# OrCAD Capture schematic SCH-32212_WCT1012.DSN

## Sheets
1 PAGE01- Revision History: title: WCT-15W1CFFPDSCT; rev: B; company: Freescale Semiconductor; note: SCH-29323 PDF: SPF-29323; note: 6501 William Cannon Drive West; note: Austin, TX 78735-8598
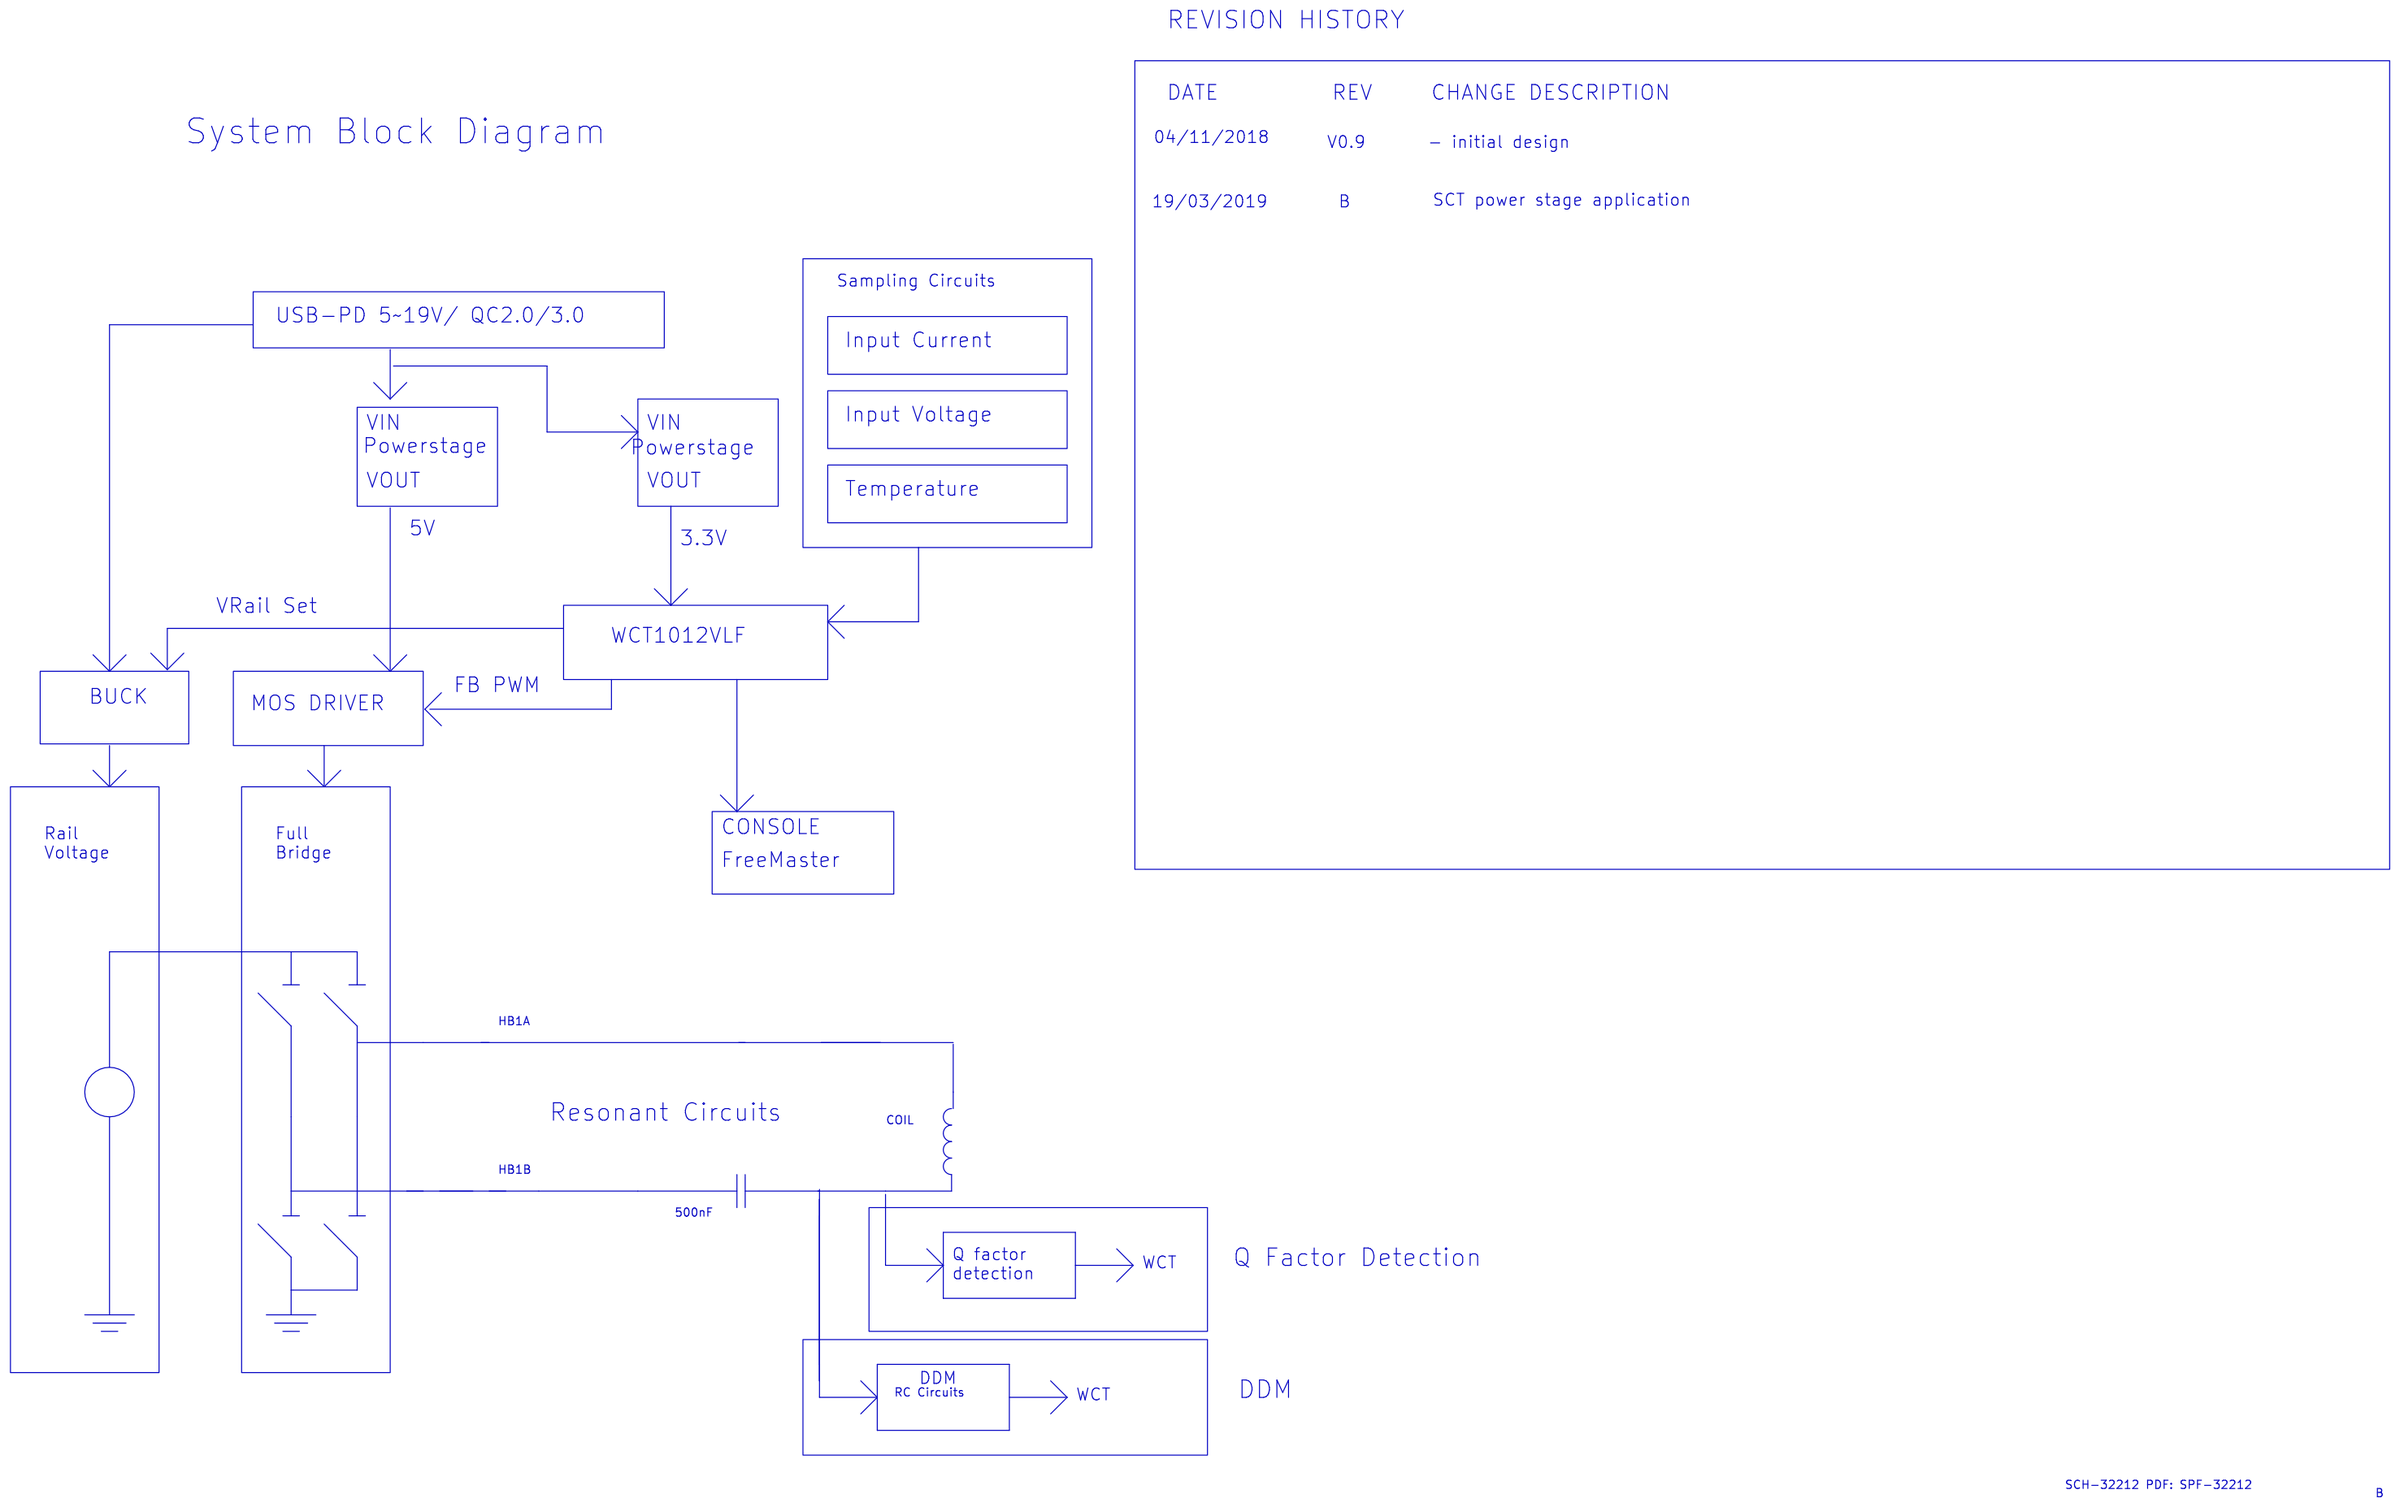
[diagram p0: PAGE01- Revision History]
2 PAGE02- Input Circuits: size B
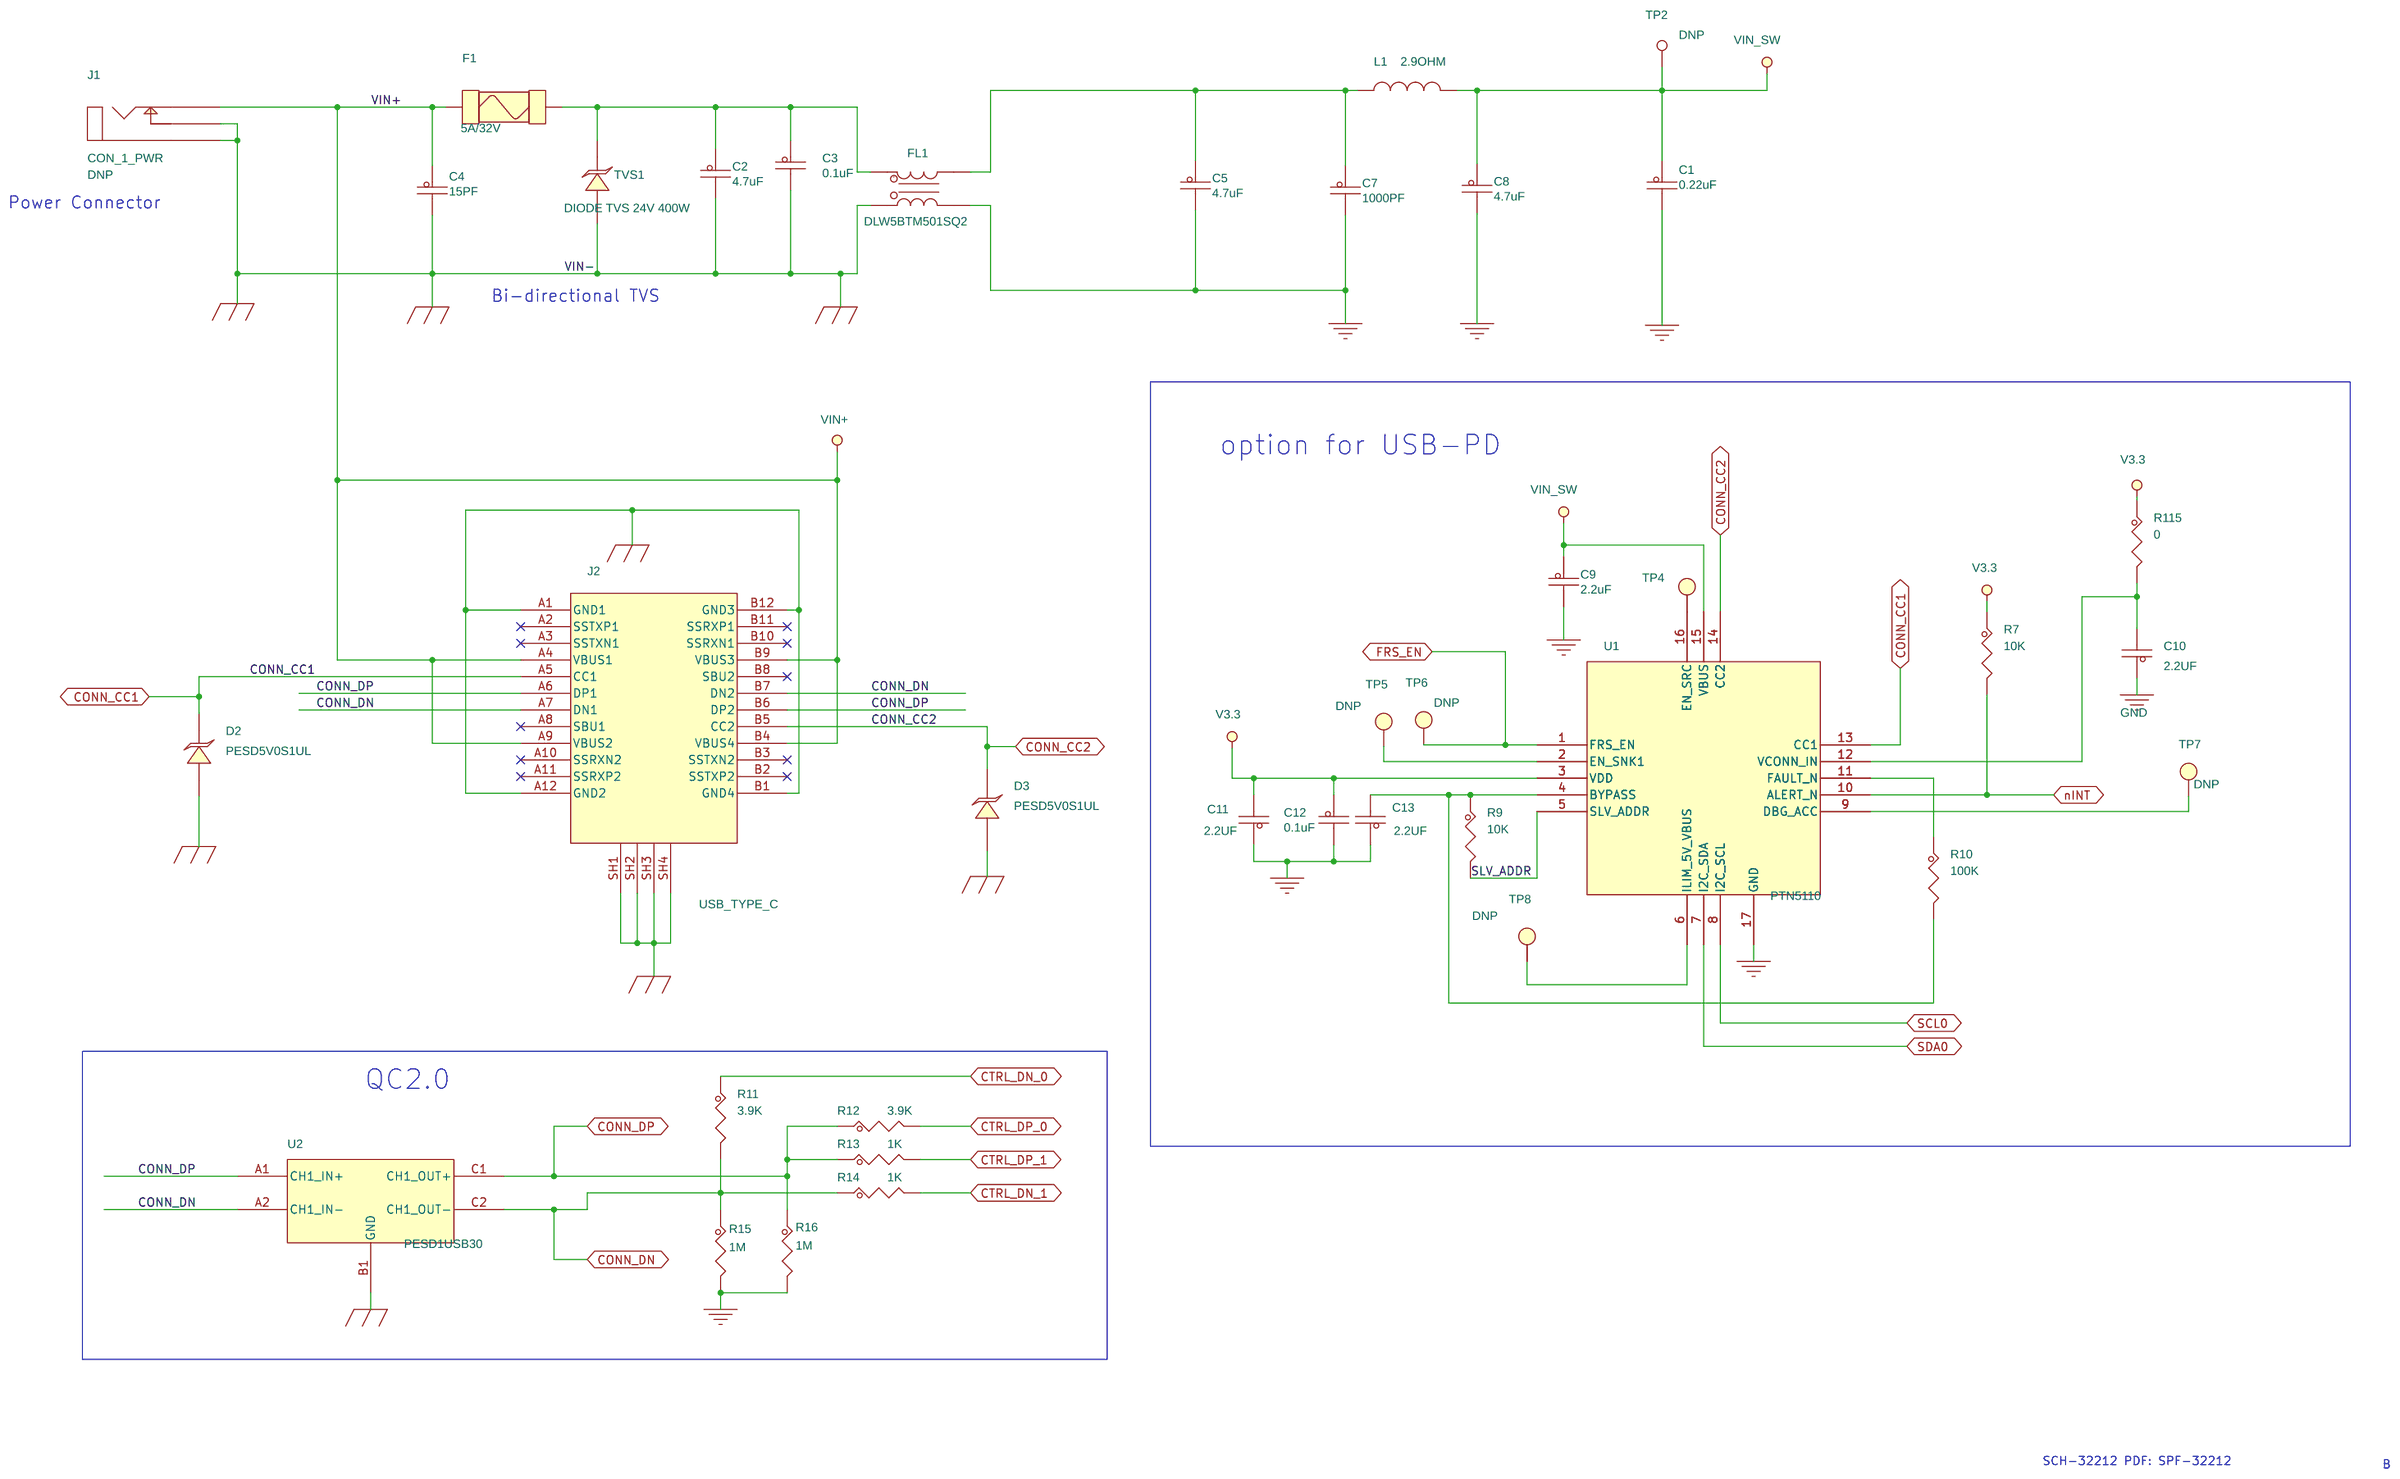
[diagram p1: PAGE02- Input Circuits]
3 PAGE03- Microprocessor: size B
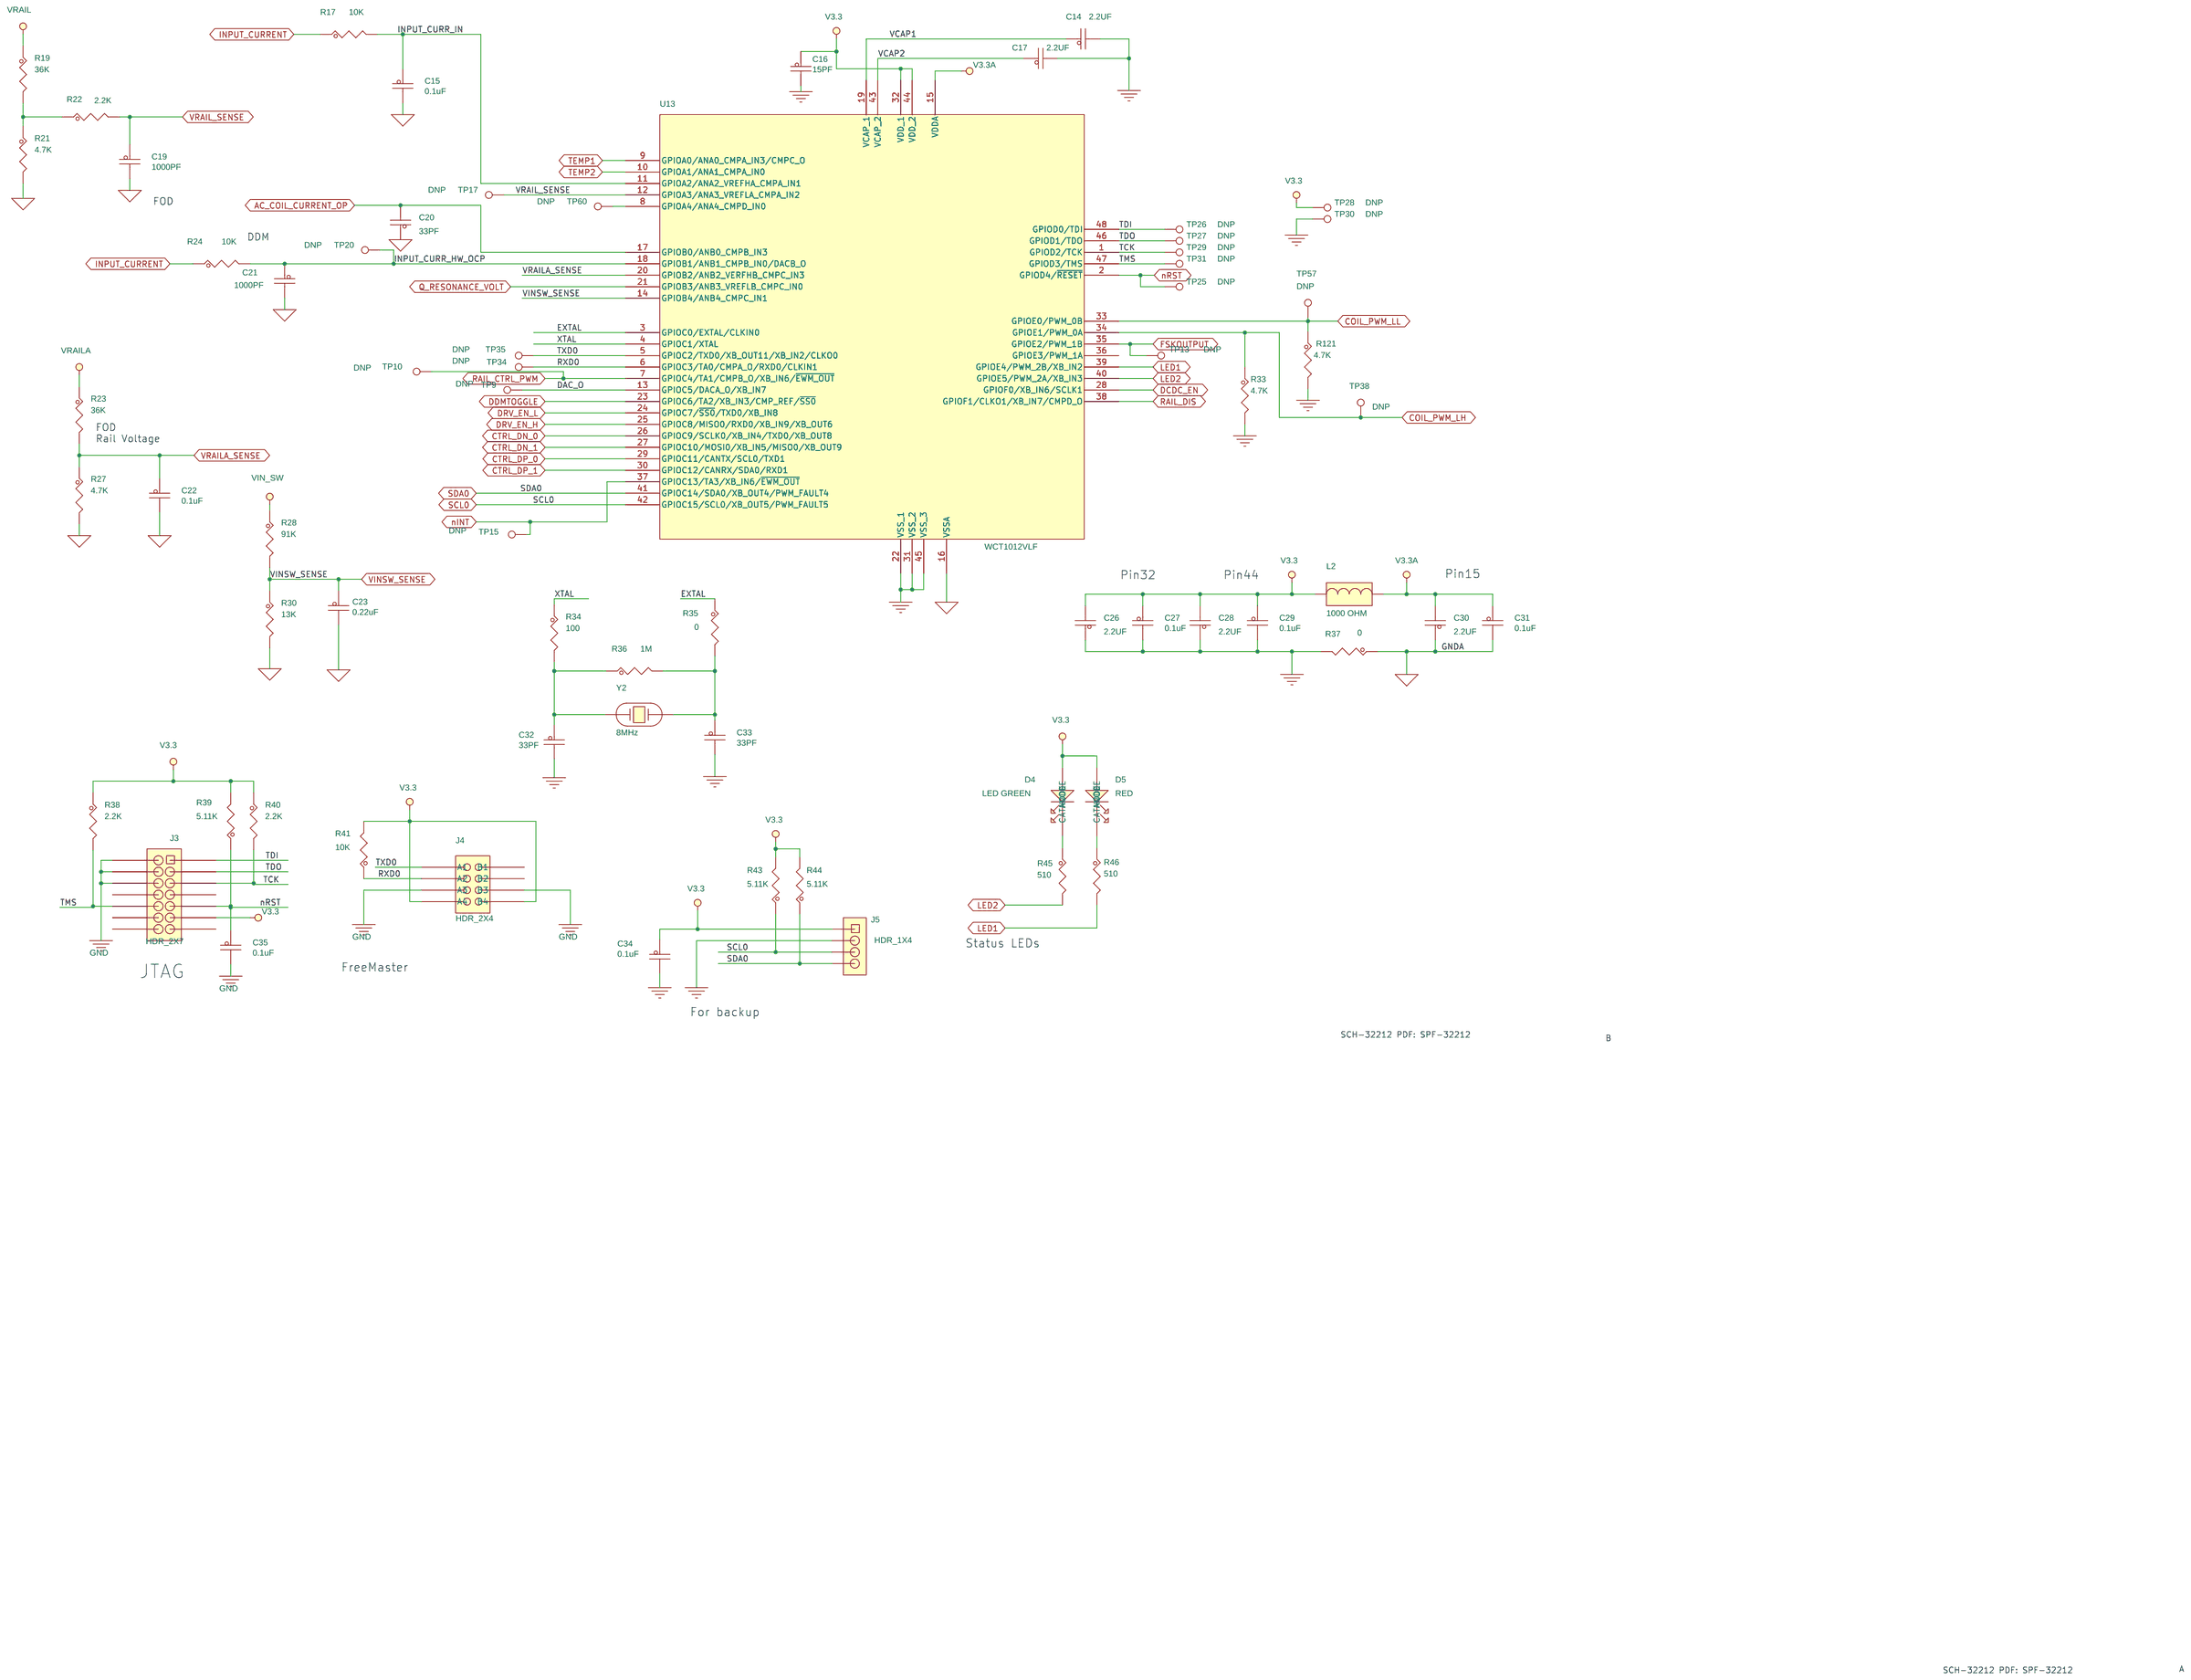
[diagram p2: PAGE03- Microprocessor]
4 PAGE04- VRail Circuits: size B
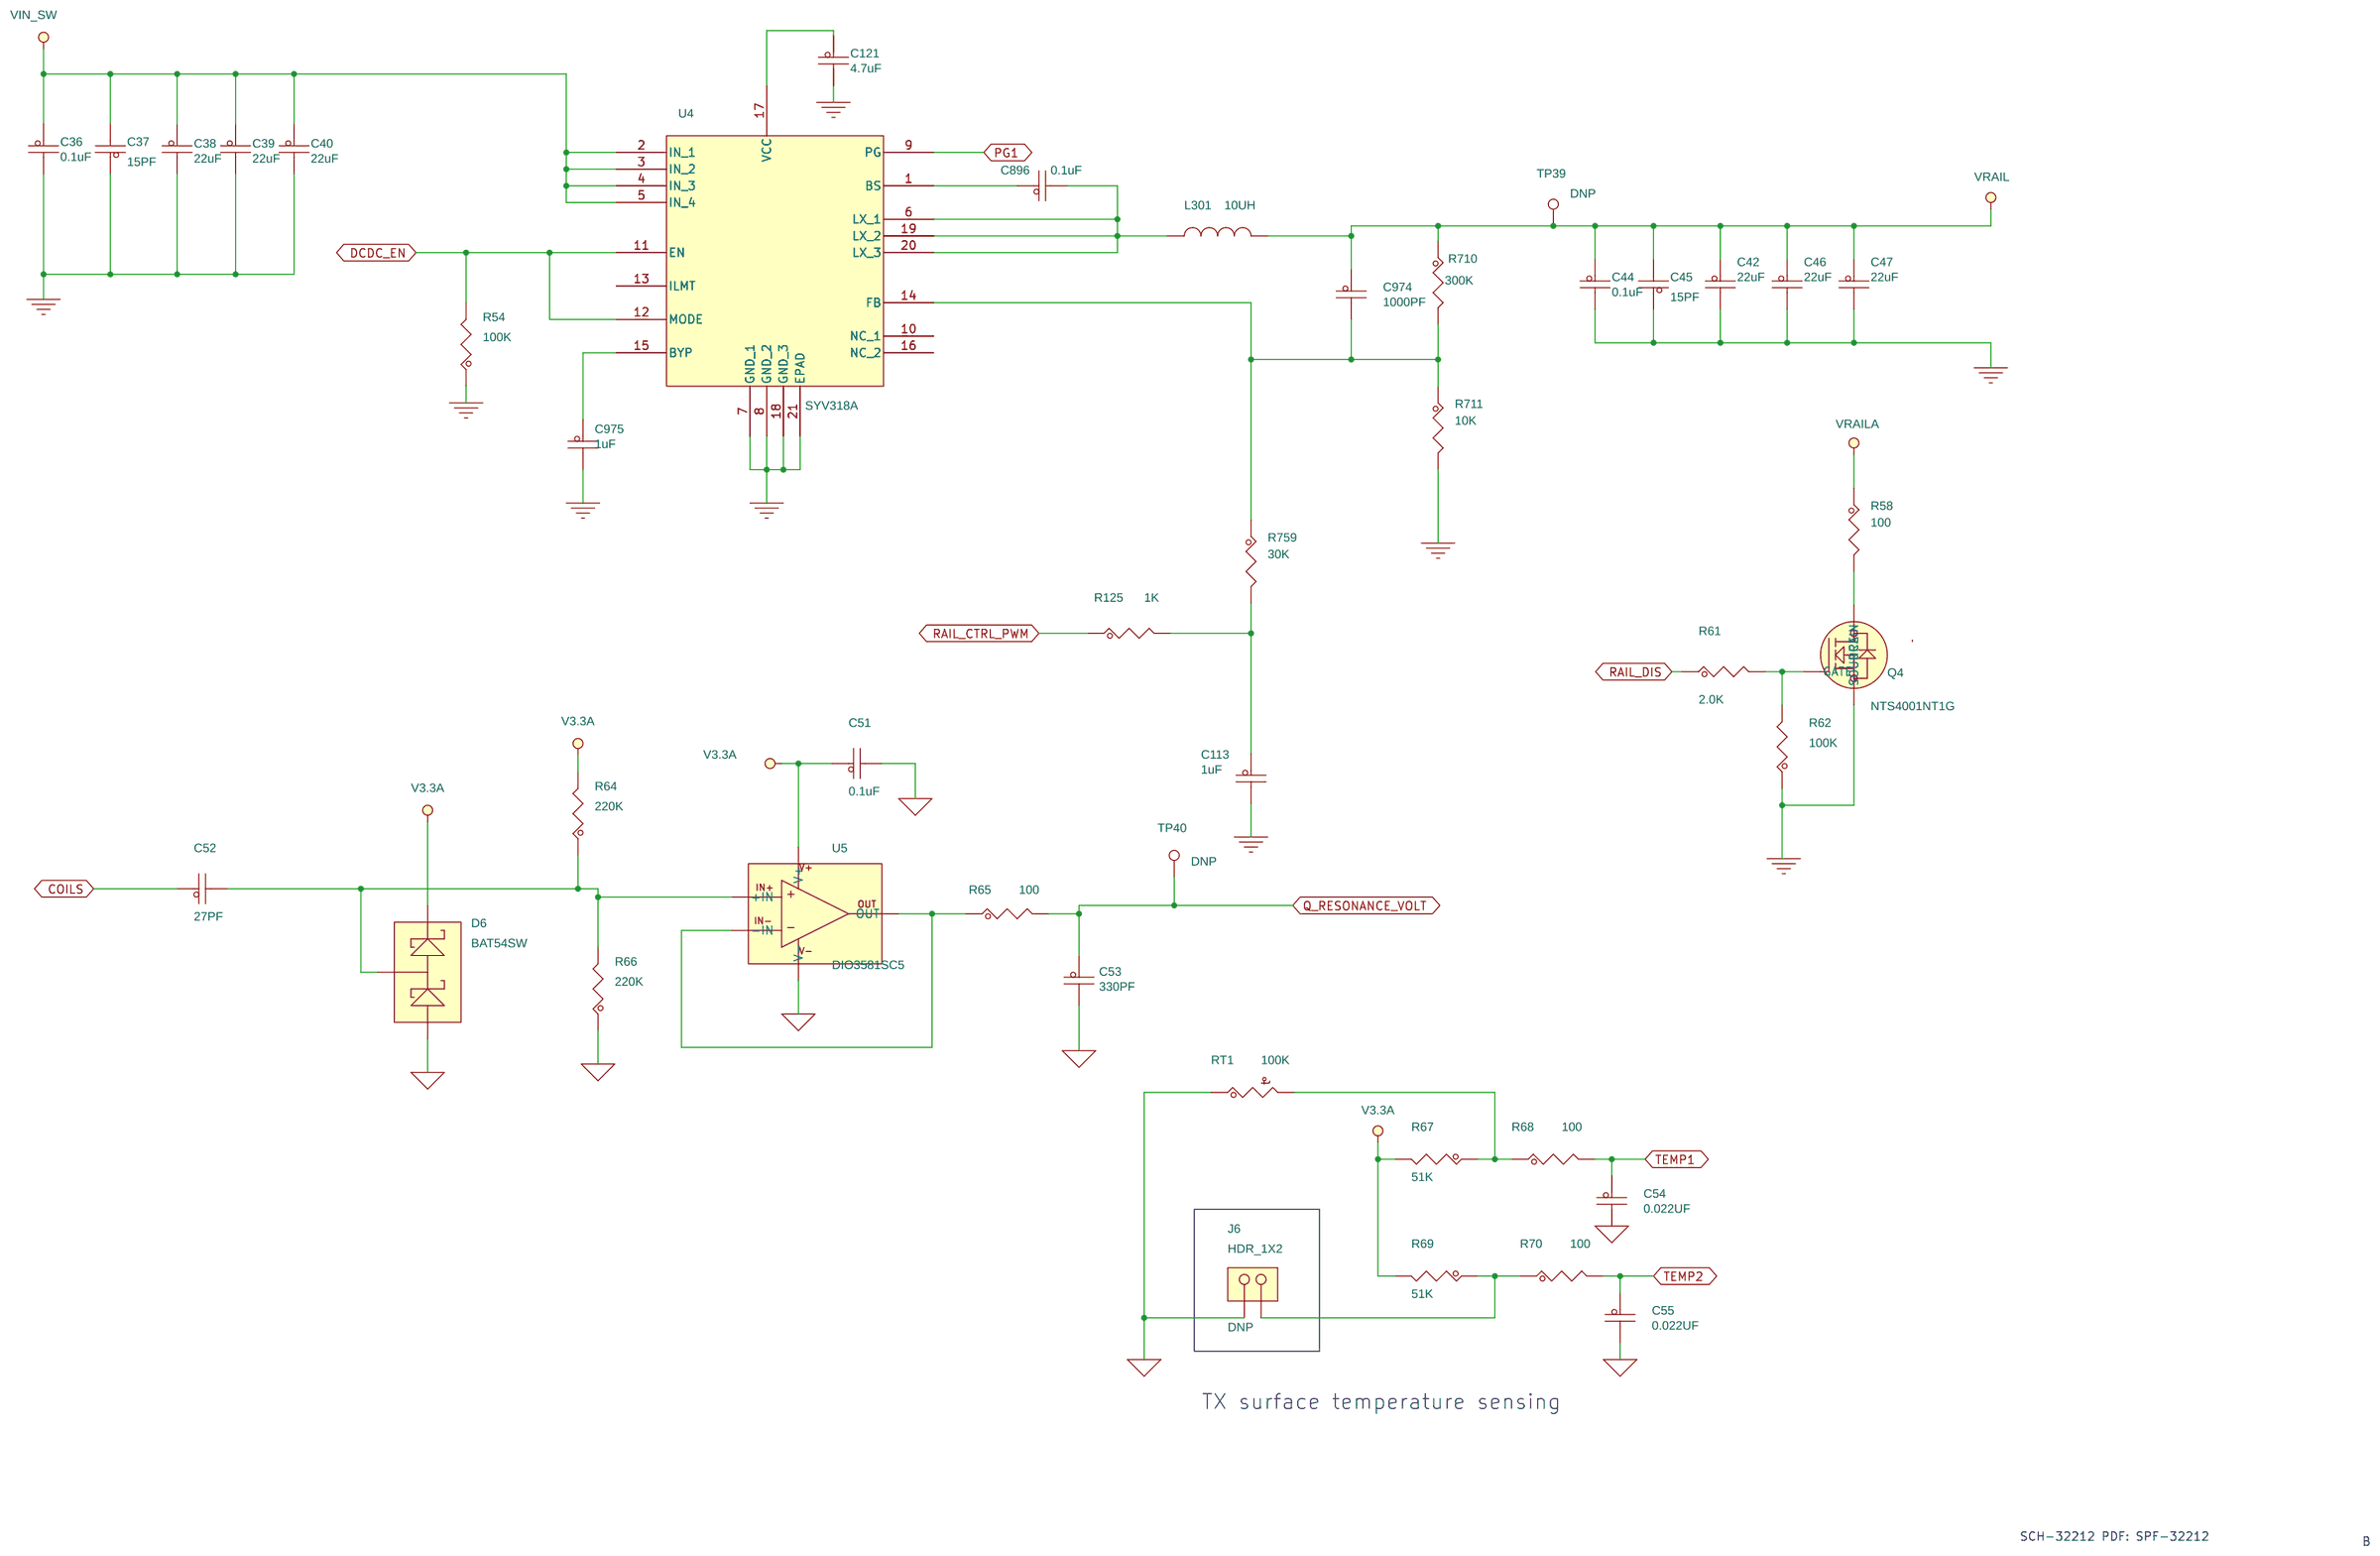
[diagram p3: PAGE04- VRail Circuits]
5 PAGE05- Power Stage: size C
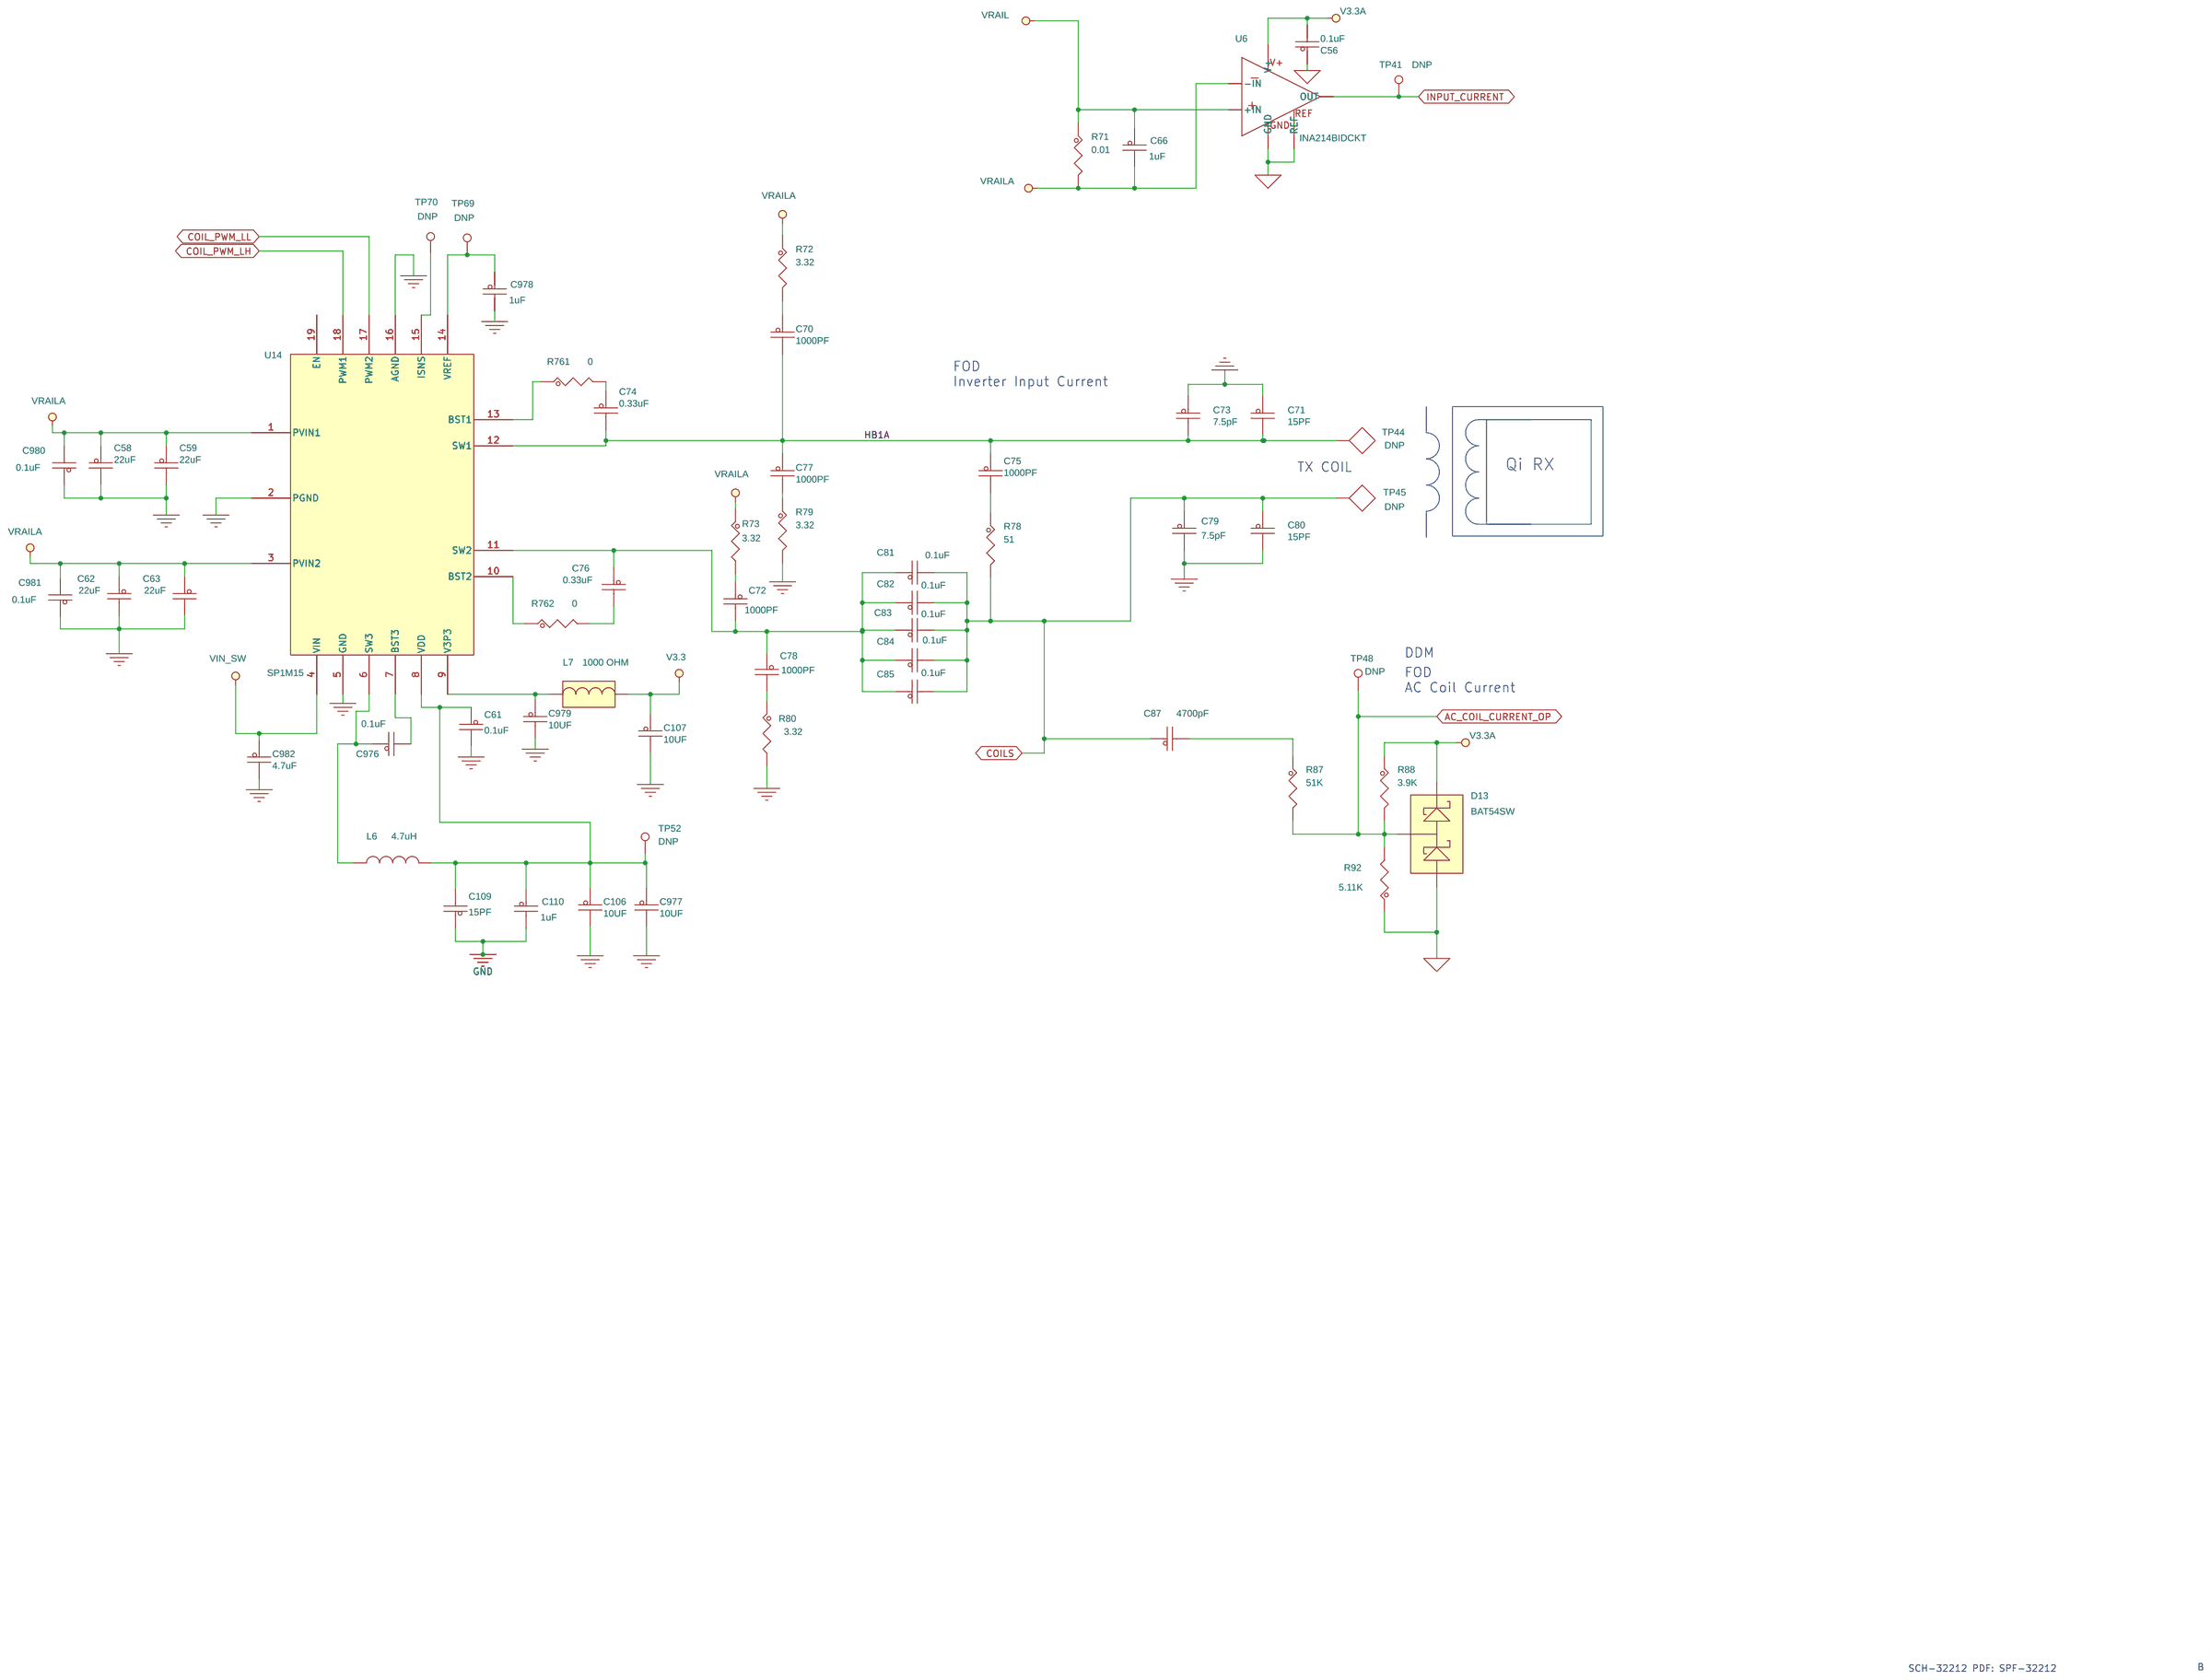
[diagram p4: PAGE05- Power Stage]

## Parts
sheet PAGE02- Input Circuits
C1  0.22uF  [CC0603_OV]
C2  4.7uF  [CC0805_OV]
C3  0.1uF  [CC0402_25]
C4  15PF  [CC0402_25]
C5  4.7uF  [CC0805_OV]
C7  1000PF  [CC0603_OV]
C8  4.7uF  [CC0805_OV]
C9  2.2uF  [CC0805_OV]
C10  2.2UF  [CC0603_OV]
C11  2.2UF  [CC0603_OV]
C12  0.1uF  [CC0402_25]
C13  2.2UF  [CC0603_OV]
D2  PESD5V0S1UL  [sod-882]
D3  PESD5V0S1UL  [sod-882]
F1  5A/32V  [fuse_3p4x1p8]
FL1  DLW5BTM501SQ2  [ind_dlw5bs_2020]
J1  CON_1_PWR  [RAPC722]
J2  USB_TYPE_C  [usb24_typec_sm_th]
L1  2.9OHM  [ind2_3p65_5p2sq_sm]
R7  10K  [RC0402_25]
R9  10K  [RC0402_25]
R10  100K  [RC0402_25]
R11  3.9K  [RC0402_25]
R12  3.9K  [RC0402_25]
R13  1K  [RC0402_25]
R14  1K  [RC0402_25]
R15  1M  [RC0402_25]
R16  1M  [RC0402_25]
R115  0  [RC0402_25]
TP2  35 MIL  [TESTPOINT_35MIL]
TP4  TP_35MIL  [testpoint_35mil]
TP5  TP_35MIL  [testpoint_35mil]
TP6  TP_35MIL  [testpoint_35mil]
TP7  TP_35MIL  [testpoint_35mil]
TP8  TP_35MIL  [testpoint_35mil]
TVS1  DIODE TVS 24V 400W  [do214ac_ak]
U1  PTN5110  [hx2qfn16_0p4_2p7x2p7]
U2  PESD1USB30  [wlcsp5_0p4_0p82x1p22]
sheet PAGE03- Microprocessor
C14  2.2UF  [CC0603_OV]
C15  0.1uF  [CC0402_25]
C16  15PF  [CC0402_25]
C17  2.2UF  [CC0603_OV]
C19  1000PF  [CC0402_25]
C20  33PF  [CC0402_25]
C21  1000PF  [CC0402_25]
C22  0.1uF  [CC0402_25]
C23  0.22uF  [CC0402_25]
C26  2.2UF  [CC0603_OV]
C27  0.1uF  [CC0402_25]
C28  2.2UF  [CC0603_OV]
C29  0.1uF  [CC0402_25]
C30  2.2UF  [CC0603_OV]
C31  0.1uF  [CC0402_25]
C32  33PF  [CC0402_25]
C33  33PF  [CC0402_25]
C34  0.1uF  [CC0402_25]
C35  0.1uF  [CC0402_25]
D4  LED GREEN  [LED_0603]
D5  RED  [LED_0603]
J3  HDR_2X7  [JUMP2X7-6040]
J4  HDR_2X4  [HDR2X4]
J5  HDR_1X4  [JUMP1X4-6040]
L2  1000 OHM  [IND_0402]
R17  10K  [RC0402_25]
R19  36K  [RC0402_25]
R21  4.7K  [RC0402_25]
R22  2.2K  [RC0402_25]
R23  36K  [RC0402_25]
R24  10K  [RC0402_25]
R27  4.7K  [RC0402_25]
R28  91K  [RC0402_25]
R30  13K  [RC0402_25]
R33  4.7K  [RC0402_25]
R34  100  [RC0402_25]
R35  0  [RC0402_25]
R36  1M  [RC0402_25]
R37  0  [RC0402_25]
R38  2.2K  [RC0402_25]
R39  5.11K  [RC0402_25]
R40  2.2K  [RC0402_25]
R41  10K  [RC0402_25]
R43  5.11K  [RC0402_25]
R44  5.11K  [RC0402_25]
R45  510  [RC0402_25]
R46  510  [RC0402_25]
R121  4.7K  [RC0402_25]
TP9  35 MIL  [TESTPOINT_35MIL]
TP10  35 MIL  [TESTPOINT_35MIL]
TP13  35 MIL  [TESTPOINT_35MIL]
TP15  35 MIL  [TESTPOINT_35MIL]
TP17  35 MIL  [TESTPOINT_35MIL]
TP20  35 MIL  [TESTPOINT_35MIL]
TP25  35 MIL  [TESTPOINT_35MIL]
TP26  35 MIL  [TESTPOINT_35MIL]
TP27  35 MIL  [TESTPOINT_35MIL]
TP28  35 MIL  [TESTPOINT_35MIL]
TP29  35 MIL  [TESTPOINT_35MIL]
TP30  35 MIL  [TESTPOINT_35MIL]
TP31  35 MIL  [TESTPOINT_35MIL]
TP34  35 MIL  [TESTPOINT_35MIL]
TP35  35 MIL  [TESTPOINT_35MIL]
TP38  35 MIL  [TESTPOINT_35MIL]
TP57  35 MIL  [TESTPOINT_35MIL]
TP60  35 MIL  [TESTPOINT_35MIL]
U13  WCT1012VLF  [LQFP48]
Y2  8MHz  [xtal2_5x3mm_sm]
sheet PAGE04- VRail Circuits
C36  0.1uF  [CC0402_25]
C37  15PF  [CC0402_25]
C38  22uF  [CC0805_OV]
C39  22uF  [CC0805_OV]
C40  22uF  [CC0805_OV]
C42  22uF  [CC0805_OV]
C44  0.1uF  [CC0402_25]
C45  15PF  [CC0402_25]
C46  22uF  [CC0805_OV]
C47  22uF  [CC0805_OV]
C51  0.1uF  [CC0402_25]
C52  27PF  [CC0603_OV]
C53  330PF  [CC0402_25]
C54  0.022UF  [CC0402_25]
C55  0.022UF  [CC0402_25]
C113  1uF  [CC0603_OV]
C121  4.7uF  [CC0603_OV]
C896  0.1uF  [CC0402_25]
C974  1000PF  [CC0402_25]
C975  1uF  [CC0603_OV]
D6  BAT54SW  [SC70_3]
J6  HDR_1X2  [HDR102]
L301  10UH  [ind2_11p5x10p3_sm]
Q4  NTS4001NT1G  [sc70_3]
R54  100K  [RC0402_25]
R58  100  [RC1206_OV]
R61  2.0K  [RC0402_25]
R62  100K  [RC0402_25]
R64  220K  [RC0402_25]
R65  100  [RC0402_25]
R66  220K  [RC0402_25]
R67  51K  [RC0402_25]
R68  100  [RC0402_25]
R69  51K  [RC0402_25]
R70  100  [RC0402_25]
R125  1K  [RC0402_25]
R710  300K  [RC0402_25]
R711  10K  [RC0402_25]
R759  30K  [RC0402_25]
RT1  100K  [RC0603_OV]
TP39  35 MIL  [TESTPOINT_35MIL]
TP40  35 MIL  [TESTPOINT_35MIL]
U4  SYV318A  [qfn20_0p45_3x3_ep043]
U5  DIO3581SC5  [sc70-5]
sheet PAGE05- Power Stage
C56  0.1uF  [CC0402_25]
C58  22uF  [CC0805_OV]
C59  22uF  [CC0805_OV]
C61  0.1uF  [CC0402_25]
C62  22uF  [CC0805_OV]
C63  22uF  [CC0805_OV]
C66  1uF  [CC0402_25]
C70  1000PF  [CC0603_OV]
C71  15PF  [CC0603_OV]
C72  1000PF  [CC0603_OV]
C73  7.5pF  [CC0603_OV]
C74  0.33uF  [CC0402_25]
C75  1000PF  [CC0603_OV]
C76  0.33uF  [CC0402_25]
C77  1000PF  [CC0603_OV]
C78  1000PF  [CC0603_OV]
C79  7.5pF  [CC0603_OV]
C80  15PF  [CC0603_OV]
C81  0.1uF  [CC1206_OV]
C82  0.1uF  [CC1206_OV]
C83  0.1uF  [CC1206_OV]
C84  0.1uF  [CC1206_OV]
C85  0.1uF  [CC1206_OV]
C87  4700pF  [CC0805_OV]
C106  10UF  [CC0805_OV]
C107  10UF  [CC0805_OV]
C109  15PF  [CC0402_25]
C110  1uF  [CC0402_25]
C976  0.1uF  [CC0402_25]
C977  10UF  [CC0805_OV]
C978  1uF  [CC0402_25]
C979  10UF  [CC0805_OV]
C980  0.1uF  [CC0402_25]
C981  0.1uF  [CC0402_25]
C982  4.7uF  [CC0805_OV]
D13  BAT54SW  [SC70_3]
L6  4.7uH  [ind_1008_smd]
L7  1000 OHM  [IND_0402]
R71  0.01  [RC1206_OV]
R72  3.32  [RC0603_OV]
R73  3.32  [RC0603_OV]
R78  51  [RC0603_OV]
R79  3.32  [RC0603_OV]
R80  3.32  [RC0603_OV]
R87  51K  [RC0402_25]
R88  3.9K  [RC0402_25]
R92  5.11K  [RC0402_25]
R761  0  [RC0402_25]
R762  0  [RC0402_25]
TP41  35 MIL  [TESTPOINT_35MIL]
TP44  10-210-3-01+  [TEST_PIN_10-201-X]
TP45  10-210-3-01+  [TEST_PIN_10-201-X]
TP48  35 MIL  [TESTPOINT_35MIL]
TP52  70 MIL  [TESTPOINT_70MIL]
TP69  35 MIL  [TESTPOINT_35MIL]
TP70  35 MIL  [TESTPOINT_35MIL]
U6  INA214BIDCKT  [sc70-6]
U14  SP1M15

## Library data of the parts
C1 = CAP_NP: CAP CER 0.22uF 50V 10% X7R 0603; AGILE_PN: 150-78919; CAD_APPROVED: Yes; FPLIST: CC0603_OV,CC0603,0603_CC; HEIGHT: 0.84MM; MFG_NAME01: CAPAX TECHNOLOGIES INC.; MFG_PN01: 0603X224K500SNT; ROHS: Yes; Tolerance: 10%; VOLTAGE: 50V
C2 C5 C8 C982 = CAP_NP: CAP CER 4.7UF 25V 10% X7R 0805; AGILE_PN: 150-75837; CAD_APPROVED: Yes; FPLIST: CC0805_OV,CC0805,0805_CC; HEIGHT: 1.4MM; MFG_NAME01: CAPAX TECHNOLOGIES INC.; MFG_PN01: 0805X475K250SNT; ROHS: Yes; Tolerance: 10%; VOLTAGE: 25V
C3 C12 C15 C22 C27 C29 C31 C34-C36 C44 C51 C56 C61 C896 C976 C980 C981 = CAP_NP: CAP CER 0.1uF 50V 10% X7R 0402; AGILE_PN: 150-79069; CAD_APPROVED: Yes; FPLIST: CC0402_25,CC0402_HD,0402_CC; HEIGHT: 0.55MM; MFG_NAME01: MURATA; MFG_PN01: GRM155R71H104KE14D; ROHS: Yes; Tolerance: 10%; VOLTAGE: 50V
C4 C16 C37 C45 C109 = CAP_NP: CAP CER 15PF 50V 5% C0G 0402; AGILE_PN: 150-30002; CAD_APPROVED: Yes; FPLIST: CC0402_25,CC0402_HD,0402_CC; HEIGHT: .55mm; MFG_NAME01: KEMET; MFG_PN01: C0402C150J5GAC; ROHS: Yes; Tolerance: 5%; VOLTAGE: 50VDC
C7 C70 C72 C77 C78 = CAP_NP: CAP CER 1000PF 50V 10% X7R 0603; AGILE_PN: 150-75140; CAD_APPROVED: YES; FPLIST: CC0603_OV,CC0603,0603_CC; HEIGHT: 0.9MM; MFG_NAME01: VENKEL COMPANY; MFG_PN01: C0603X7R500-102KNE; ROHS: Yes; Tolerance: 10%; VOLTAGE: 50V
C9 = CAP_NP: CAP CER 2.2UF 50V 10% X7R 0805; AGILE_PN: 150-79433; CAD_APPROVED: Yes; FPLIST: CC0805_OV,CC0805,0805_CC; HEIGHT: 1.45M; MFG_NAME01: TAIYO YUDEN; MFG_PN01: UMK212BB7225KG-T; ROHS: Yes; Tolerance: 10%; VOLTAGE: 50V
C10 C11 C13 C14 C17 C26 C28 C30 = CAP_NP: CAP CER 2.2UF 6.3V 10% X7R 0603; AGILE_PN: 150-76233; CAD_APPROVED: Yes; FPLIST: CC0603_OV,CC0603,0603_CC; HEIGHT: 1.25MM; MFG_NAME01: SMEC; MFG_PN01: MCCJ225K1NRTF; ROHS: Yes; Tolerance: 10%; VOLTAGE: 6.3V
D2 D3 = DIODE_TVS: DIODE TVS UNIDIR 5V AEC-Q101 SOD882; AGILE_PN: 480-79614; CAD_APPROVED: Yes; HEIGHT: 0.5MM; MFG_NAME01: NEXPERIA; MFG_PN01: PESD5V0S1UL,315; ROHS: Yes
F1 = FUSE: FUSE FAST 5A 32V SMT; AGILE_PN: 510-77398; CAD_APPROVED: Yes; HEIGHT: 1.09MM; MFG_NAME01: COOPER BUSSMANN; MFG_PN01: 3216FF5-R; ROHS: Yes
FL1 = DLW43: IND CHK 500OHM@100MHZ 4A -- 2020; AGILE_PN: 180-78138; CAD_APPROVED: Yes; HEIGHT: 2.5MM; MFG_NAME01: Murata; PART_TYPE: CHOKE; ROHS: Yes
J1 = PHONE_JACK: CON1 PWR PLUG RA 5A--430H IN; AGILE_PN: 210-75818; ASSY_OPT: DNP; CAD_APPROVED: Yes; HEIGHT: 11.0MM; MFG_NAME01: SWITCHCRAFT; MFG_PN01: RAPC722X; ROHS: Yes
J2 = USB24_TYPEC: CON24 USB_TYPE_C HYBRID TOP_MOUNT 0.5MM RA SHLD SKT SMT SP 139H AU 31L; AGILE_PN: 210-80990; CAD_APPROVED: Yes; HEIGHT: 3.53MM; MFG_NAME01: Amphenol; MFG_PN01: 12401548E4#2A; ROHS: Yes
L1 = INDUCTOR: IND -- 2.9OHM@1MHz 4000mA SMD; AGILE_PN: 180-78353; CAD_APPROVED: Yes; HEIGHT: 2.2MM; MFG_NAME01: MURATA; MFG_PN01: NFZ5BBW2R9LN10L; ROHS: Yes
R7 R9 R17 R24 R41 = RES: RES MF 10K 1/16W 1% 0402; AGILE_PN: 470-80452; CAD_APPROVED: Yes; FPLIST: RC0402_25,RC0402_HD,0402_CC; HEIGHT: 0.40 MM; MFG_NAME01: yageo; MFG_PN01: RC0402FR-1310KL; ROHS: Yes; Tolerance: 1%
R10 = RES: RES MF 100K 1/16W 5% 0402; AGILE_PN: 470-75597; CAD_APPROVED: Yes; FPLIST: RC0402_25,RC0402_HD,0402_CC; HEIGHT: 0.40 MM; MFG_NAME01: VENKEL COMPANY; MFG_PN01: CR0402-16W-104JT; ROHS: Yes; Temp_Range: -55C to +155C; Tolerance: 5%
R11 R12 R88 = RES: RES MF 3.90K 1/16W 1% 0402; AGILE_PN: 470-76036; CAD_APPROVED: Yes; FPLIST: RC0402_25,RC0402_HD,0402_CC; HEIGHT: 0.4 MM; MFG_NAME01: BOURNS; MFG_PN01: CR0402-FX-3901GLF; ROHS: Yes; Tolerance: 1%
R13 R14 = RES: RES MF 1.0K 1/16W 5% 0402; AGILE_PN: 470-75555; CAD_APPROVED: Yes; FPLIST: RC0402_25,RC0402_HD,RC0402_X2,0402_CC; HEIGHT: 0.41mm; MFG_NAME01: VISHAY INTERTECHNOLOGY; MFG_PN01: CRCW04021K00JNED; ROHS: Yes; Tolerance: 5%
R15 R16 R36 = RES: RES MF 1M 1/16W 1% 0402; AGILE_PN: 470-80575; CAD_APPROVED: Yes; FPLIST: RC0402_25,RC0402_HD,0402_CC; HEIGHT: 0.4MM; MFG_NAME01: BOURNS; MFG_PN01: CR0402-FX-1004GLF; ROHS: Yes; Tolerance: 1%
R35 R37 R115 R761 R762 = RES: RES MF ZERO OHM 1/10W -- 0402; AGILE_PN: 470-79965; CAD_APPROVED: Yes; FPLIST: RC0402_25,RC0402_HD,RC0402_X2,0402_CC; HEIGHT: 0.4MM; MFG_NAME01: Panasonic; MFG_PN01: ERJ-2GE0R00X; ROHS: Yes
TP2 TP9 TP10 TP13 TP15 TP17 TP20 TP25-TP31 TP34 TP35 TP38-TP41 TP48 TP57 TP60 TP69 TP70 = Test_pad: TEST PAD 35 MIL ROUND SMT; NO PART TO ORDER; AGILE_PN: 510-75219; ASSY_OPT: DNP; CAD_APPROVED: Yes; HEIGHT: 0.1 MM; ROHS: Yes
TP4 = T_POINT_R: TEST POINT PAD .035 SMT, no part to order; AGILE_PN: 510-75618; CAD_APPROVED: Yes; HEIGHT: 0.1MM; ROHS: Yes
TP5-TP8 = T_POINT_R: TEST POINT PAD .035 SMT, no part to order; AGILE_PN: 510-75618; ASSY_OPT: DNP; CAD_APPROVED: Yes; HEIGHT: 0.1MM; ROHS: Yes
TVS1 = DIODE_TVS: DIODE TVS -- 24V 400W DO-214AC; AGILE_PN: 480-75498; CAD_APPROVED: Yes; HEIGHT: 2.29MM; MFG_NAME01: LITTELFUSE; MFG_PN01: SMAJ24CA; ROHS: Yes
U1 = PTN5110_16P_EP: IC USB PD PHY 1PORT 2.7-5.5V HX2QFN16; AGILE_PN: 315-81118; CAD_APPROVED: Yes; HEIGHT: 0.4MM; MFG_NAME01: NXP SEMICONDUCTORS; MFG_PN01: PTN5110NHQZ; ROHS: Yes; Temp_Range: ¨C40C to +85C
U2 = PESD1USB30: DIODE ESD USB 5V WLCSP5; AGILE_PN: 315-81117; CAD_APPROVED: Yes; HEIGHT: 0.6MM; MFG_NAME01: NEXPERIA; MFG_PN01: PESD1USB3S; ROHS: Yes
C19 = CAP_NP: CAP CER 1000PF 50V 10% X7R 0402; AGILE_PN: 150-75271; CAD_APPROVED: Yes; FPLIST: CC0402_25,CC0402_HD,0402_CC; HEIGHT: 0.635 MM; MFG_NAME01: AVX; MFG_PN01: 04025C102KAT2A; ROHS: Yes; Tolerance: +10%; VOLTAGE: 50VDC
C20 C32 C33 = CAP_NP: CAP CER 33PF 50V 5% C0G 0402; AGILE_PN: 150-30000; CAD_APPROVED: Yes; FPLIST: CC0402_25,CC0402_HD,0402_CC; HEIGHT: 0.635MM; MFG_NAME01: VENKEL COMPANY; MFG_PN01: C0402C0G500-330JNE; ROHS: Yes; Tolerance: 5%; VOLTAGE: 50VDC
C21 = CAP_NP: CAP CER 1000PF 25V 10% X7R 0402; AGILE_PN: 150-75269; CAD_APPROVED: Yes; FPLIST: CC0402_25,CC0402_HD,0402_CC; HEIGHT: 0.635MM; MFG_NAME01: VENKEL COMPANY; MFG_PN01: C0402X7R250-102KNE; ROHS: Yes; Tolerance: 10%; VOLTAGE: 25V
C23 = CAP_NP: CAP CER 0.22UF 16V 10% X7R 0402; AGILE_PN: 150-78886; CAD_APPROVED: Yes; FPLIST: CC0402_25,CC0402_HD,0402_CC; HEIGHT: 0.55MM; MFG_NAME01: Murata; MFG_PN01: GRM155R71C224KA12D; ROHS: Yes; Tolerance: 10%; VOLTAGE: 16V
D4 = LED: LED GRN SGL 20MA 0603; AGILE_PN: 370-76565; CAD_APPROVED: Yes; HEIGHT: 0.67MM; MFG_NAME01: osram; MFG_PN01: LG L29K-G2J1-24-Z; ROHS: Yes
D5 = LED: LED RED SGL 20MA SMT; AGILE_PN: 370-76568; CAD_APPROVED: Yes; HEIGHT: 0.67MM; MFG_NAME01: OSRAM; MFG_PN01: LS L29K-H1J2-1; ROHS: Yes
J3 = HDR-2X7: HDR 2X7 TH 100MIL CTR 330H AU 105L; AGILE_PN: 210-75689; CAD_APPROVED: Yes; FPLIST: JUMP2X7-6040,HDR2X7; HEIGHT: 8.38 MM; MFG_NAME01: SAMTEC; MFG_PN01: TSW-107-07-S-D; ROHS: Yes
J4 = CONN_HDR_4X2: HDR 2X4 TH 100MIL CTR 338H AU 120L; AGILE_PN: 210-79807; CAD_APPROVED: Yes; HEIGHT: 8.6MM; MFG_NAME01: SULLINS ELECTRONICS CORP; MFG_PN01: PBC04DAAN; ROHS: Yes
J5 = HDR-1X4: HDR 1X4 TH 100MIL SP  336H AU 100L; AGILE_PN: 210-75688; CAD_APPROVED: Yes; HEIGHT: 8.4mm; MFG_NAME01: SAMTEC; MFG_PN01: TSW-104-07-G-S; ROHS: Yes
L2 L7 = BEAD: IND FER BEAD 1000 OHM@100MHZ 200MA 25% 0402; AGILE_PN: 180-76937; CAD_APPROVED: Yes; FPLIST: IND_0402,0402_CC; HEIGHT: 0.55MM; MFG_NAME01: Murata; MFG_PN01: BLM15AG102SN1D; PART_TYPE: FERRITE\BEAD; ROHS: Yes
R19 R23 = RES: RES MF 36K  1/10W 1% AEC-Q200 0402; AGILE_PN: 470-31009; CAD_APPROVED: Yes; FPLIST: RC0402_25,RC0402_HD,0402_CC; HEIGHT: 0.40 MM; MFG_NAME01: KOA SPEER; MFG_PN01: RK73H1ETTP3602F; ROHS: Yes; Temp_Range: -55C to +155C; Tolerance: 1%
R21 R27 R33 R121 = RES: RES MF 4.7K OHM 1/16W 1% 0402; AGILE_PN: 470-80911; CAD_APPROVED: Yes; FPLIST: RC0402_25,RC0402_HD,0402_CC; HEIGHT: 0.4MM; MFG_NAME01: yageo; MFG_PN01: RC0402FR-074K7L; ROHS: Yes; Tolerance: 1%
R22 R38 R40 = RES: RES MF 2.2K 1/16W 1% 0402; AGILE_PN: 470-78359; CAD_APPROVED: Yes; FPLIST: RC0402_25,RC0402_HD,0402_CC; HEIGHT: 0.4MM; MFG_NAME01: WALSIN TECHNOLOGY CORP.; MFG_PN01: WR04X2201FTL; ROHS: Yes; Temp_Range: -55C to +155C; Tolerance: 1%
R28 = RES: RES MF 91K 1/10W 1% AEC-Q200 0402; AGILE_PN: 470-31057; CAD_APPROVED: Yes; FPLIST: RC0402_25,RC0402_HD,0402_CC; HEIGHT: 0.40 MM; MFG_NAME01: KOA SPEER; MFG_PN01: RK73H1ETTP9102F; ROHS: Yes; Temp_Range: -55C to +155C; Tolerance: 1%
R30 = RES: RES MF 13K 1/10W 1% AEC-Q200 0402; AGILE_PN: 470-30959; CAD_APPROVED: Yes; FPLIST: RC0402_25,RC0402_HD,0402_CC; HEIGHT: 0.40 MM; MFG_NAME01: KOA SPEER; MFG_PN01: RK73H1ETTP1302F; ROHS: Yes; Temp_Range: -55C to +155C; Tolerance: 1%
R34 R65 R68 R70 = RES: RES MF 100 OHM 1/16W 1% 0402; AGILE_PN: 470-30454; CAD_APPROVED: Yes; FPLIST: RC0402_25,RC0402_HD,0402_CC; HEIGHT: 0.4 MM; MFG_NAME01: THYE MING TECH CO LTD; MFG_PN01: CR-02FL6--100R; ROHS: Yes; Tolerance: 1%
R39 R43 R44 R92 = RES: RES MF 5.11K 1/16W 1% 0402; AGILE_PN: 470-76128; CAD_APPROVED: Yes; FPLIST: RC0402_25,RC0402_HD,0402_CC; HEIGHT: 0.4 MM; MFG_NAME01: BOURNS; MFG_PN01: CR0402-FX-5111GLF; ROHS: Yes; Tolerance: 1%
R45 R46 = RES: RES MF 510 OHM 1/16W 1% 0402; AGILE_PN: 470-76479; CAD_APPROVED: Yes; FPLIST: RC0402_25,RC0402_HD,0402_CC; HEIGHT: 0.4MM; MFG_NAME01: THYE MING TECH CO LTD; MFG_PN01: CR-02FL6--510R; ROHS: Yes; Tolerance: 1%
U13 = MC56F82726_LQFP48: IC DSC 32BIT 32K FLASH 6K RAM 100MHZ 3-3.6V LQFP48; AGILE_PN: 312-80821; CAD_APPROVED: Yes; HEIGHT: 1.6 MM; MFG_NAME01: FREESCALE SEMICONDUCTOR; ROHS: Yes
Y2 = XTAL: XTAL 8MHZ 20PPM PAR 18PF ESR 120OHM SMT; AGILE_PN: 230-78285; CAD_APPROVED: Yes; HEIGHT: 1.4MM; MFG_NAME01: HOSONIC ELECTRONIC CO., LTD.; MFG_PN01: E5FA8E0006900E; ROHS: Yes
C38-C40 C42 C46 C47 C58 C59 C62 C63 = CAP_NP: CAP CER 22uF 25V 20% X5R 0805; AGILE_PN: 150-79304; CAD_APPROVED: Yes; FPLIST: CC0805_OV,CC0805,0805_CC; HEIGHT: 1.45MM; MFG_NAME01: MURATA; MFG_PN01: GRM21BR61E226ME44; ROHS: Yes; Tolerance: 20%; VOLTAGE: 25V
C52 = CAP_NP: CAP CER 27PF 50V 5% C0G 0603; AGILE_PN: 150-75276; CAD_APPROVED: YES; FPLIST: CC0603_OV,CC0603,0603_CC; HEIGHT: 0.9MM; MFG_NAME01: AVX; MFG_PN01: 06035A270JAT2A; ROHS: Yes; Tolerance: 5%; VOLTAGE: 50V
C53 = CAP_NP: CAP CER 330PF 16V 10% X7R 0402; AGILE_PN: 150-75270; CAD_APPROVED: Yes; FPLIST: CC0402_25,CC0402_HD,0402_CC; HEIGHT: 0.55MM; MFG_NAME01: KEMET; MFG_PN01: C0402C331K4RAC; ROHS: Yes; Tolerance: 10%; VOLTAGE: 50V
C54 C55 = CAP_NP: CAP CER 0.022UF 16V 10% X7R 0402; AGILE_PN: 150-30293; CAD_APPROVED: Yes; FPLIST: CC0402_25,CC0402_HD,0402_CC; HEIGHT: 0.56MM; MFG_NAME01: AVX; MFG_PN01: 0402YC223KAT2A; ROHS: Yes; Tolerance: 10%; VOLTAGE: 16V
C113 C975 = CAP_NP: CAP CER 1UF 25V 10% X7R 0603; AGILE_PN: 150-30185; CAD_APPROVED: Yes; FPLIST: CC0603_OV,CC0603,0603_CC; HEIGHT: 0.9mm; MFG_NAME01: CAPAX TECHNOLOGIES INC.; MFG_PN01: 0603X105K250SNT; ROHS: Yes; Tolerance: 10%; VOLTAGE: 25V
C121 = CAP_NP: CAP CER 4.7uF 25V 10% X5R 0603; AGILE_PN: 150-79317; CAD_APPROVED: Yes; FPLIST: CC0603_OV,CC0603,0603_CC; HEIGHT: 0.95MM; MFG_NAME01: Murata; MFG_PN01: GRM188R61E475KE11D; ROHS: Yes; Tolerance: 10%; VOLTAGE: 25V
C974 = CAP_NP: CAP CER 1000PF 50V 10% X7R 0402; AGILE_PN: 150-75271; CAD_APPROVED: Yes; FPLIST: CC0402_25,CC0402_HD,0402_CC,CAPC0402_L; HEIGHT: 0.635 MM; MFG_NAME01: AVX; MFG_PN01: 04025C102KAT2A; ROHS: Yes; Tolerance: +10%; VOLTAGE: 50VDC
D6 D13 = BAT54SW: DIODE SCH DUAL 200MA 30V SOT323; AGILE_PN: 480-77935; CAD_APPROVED: Yes; HEIGHT: 1.1MM; MFG_NAME01: NEXPERIA; MFG_PN01: BAT54SW,115; ROHS: Yes
J6 = CONN_HDR_2X1: HDR 1X2 TH 100MIL SP 378H AU 130L; AGILE_PN: 210-75673; ASSY_OPT: DNP; CAD_APPROVED: Yes; HEIGHT: 9.6 MM; MFG_NAME01: TYCO ELECTRONICS; MFG_PN01: 826629-2; ROHS: Yes
L301 = INDUCTOR: IND PWR 10UH@100KHZ 7.2A 20% SMD; AGILE_PN: 180-78836; CAD_APPROVED: Yes; HEIGHT: 4MM; MFG_NAME01: CYNTEC; MFG_PN01: CMLB104T-100MS; PART_TYPE: POWER; ROHS: Yes; Temp_Range: -55° C to +125° C; Tolerance: 20%
Q4 = MOSFET_N: TRAN NMOS SW 30V 270MA SC-70; AGILE_PN: 480-76278; CAD_APPROVED: Yes; HEIGHT: 1.0MM; MFG_NAME01: ON SEMICONDUCTOR; ROHS: Yes
R54 = RES: RES MF 100K 1/16W 1% 0402; AGILE_PN: 470-76240; CAD_APPROVED: Yes; FPLIST: RC0402_25,RC0402_HD,0402_CC; HEIGHT: 0.4MM; MFG_NAME01: NIC COMPONENTS CORP; MFG_PN01: NRCL04F1003TRF; ROHS: Yes; Tolerance: 1%
R58 = RES: RES MF 100 OHM 1/4W 1% 1206; AGILE_PN: 470-30055; CAD_APPROVED: Yes; FPLIST: RC1206_OV,RC1206,1206_CC; HEIGHT: 0.6MM; MFG_NAME01: VISHAY INTERTECHNOLOGY; MFG_PN01: CRCW1206100RFKEA; ROHS: Yes; Tolerance: 1%
R61 = RES: RES MF 2.0K 1/16W 1% 0402; AGILE_PN: 470-75356; CAD_APPROVED: Yes; FPLIST: RC0402_25,RC0402_HD,0402_CC; HEIGHT: 0.4mm; MFG_NAME01: BOURNS; MFG_PN01: CR0402-FX-2001GLF; ROHS: Yes; Tolerance: 1%
R62 = RES: RES MF 100K 1/16W 1% 0402; AGILE_PN: 470-76240; CAD_APPROVED: Yes; FPLIST: RC0402_25,RC0402_HD,0402_CC; HEIGHT: 0.4MM; MFG_NAME01: YAGEO AMERICA; MFG_PN01: RC0402FR-07100KL; ROHS: Yes; Tolerance: 1%
R64 R66 = RES: RES MF 220K  1/16W 1% 0402; AGILE_PN: 470-31097; CAD_APPROVED: Yes; FPLIST: RC0402_25,RC0402_HD,0402_CC; HEIGHT: 0.40 MM; MFG_NAME01: VIKING TECH CORPORATION; MFG_PN01: CR-02FL6--220K; ROHS: Yes; Tolerance: 1%
R67 R69 R87 = RES: RES MF 51K  1/16W 1% 0402; AGILE_PN: 470-31027; CAD_APPROVED: Yes; FPLIST: RC0402_25,RC0402_HD,0402_CC; HEIGHT: 0.40 MM; MFG_NAME01: YAGEO AMERICA; MFG_PN01: RC0402FR-0751KL; ROHS: Yes; Tolerance: 1%
R125 = RES: RES MF 1K 1/16W 0.5% 0402; AGILE_PN: 470-80057; CAD_APPROVED: Yes; FPLIST: RC0402_25,RC0402_HD,0402_CC; HEIGHT: 0.4MM; MFG_NAME01: Panasonic; MFG_PN01: ERA2AED102X; ROHS: Yes; Tolerance: 0.5%
R710 = RES: RES MF 300K 1/10W 1% AEC-Q200 0402; AGILE_PN: 470-31112; CAD_APPROVED: Yes; FPLIST: RC0402_25,RC0402_HD,0402_CC; HEIGHT: 0.40 MM; MFG_NAME01: KOA SPEER; MFG_PN01: RK73H1ETTP3003F; ROHS: Yes; Temp_Range: -55C to +155C; Tolerance: 1%
R711 = RES: RES MF 10K 1/16W 1% 0402; AGILE_PN: 470-80452; CAD_APPROVED: Yes; FPLIST: RC0402_25,RC0402_HD,0402_CC,RC0402_X2; HEIGHT: 0.40 MM; MFG_NAME01: NIC COMPONENTS CORP; MFG_PN01: NRCL04F1002TRF; ROHS: Yes; Tolerance: 1%
R759 = RES: RES MF 30K 1/10W 1% AEC-Q200 0402; AGILE_PN: 470-81708; CAD_APPROVED: Yes; FPLIST: RC0402_25,RC0402_HD,0402_CC; HEIGHT: 0.40 MM; MFG_NAME01: KOA SPEER; MFG_PN01: RK73H1ETTP3002F; ROHS: Yes; Temp_Range: -55C to +155C; Tolerance: 1%
RT1 = THERMISTOR: THERMISTOR NTC 100K@25 DEGC 1% 0603; AGILE_PN: 470-79984; CAD_APPROVED: Yes; FPLIST: RC0603_OV,RC0603,0603_CC; HEIGHT: 0.9MM; MFG_NAME01: TDK; MFG_PN01: NTCG164KF104F; ROHS: Yes; Tolerance: 1%
U4 = SY8286ARAC_QFN20: IC REG DC-DC BUCK SW 6A 4-23V QFN20; AGILE_PN: 315-82066; CAD_APPROVED: Yes; HEIGHT: 0.9 MM; MFG_NAME01: SILERGY CORP.; MFG_PN01: SY8286ARAC; ROHS: Yes; Temp_Range: -40° C to + 85° C
U5 = LMV301: IC LIN OPAMP SGL LOW PWR 2-5.5V SC70-5; AGILE_PN: 315-82019; CAD_APPROVED: Yes; HEIGHT: 1.05MM; MFG_NAME01: DIOO MICROCIRCUITS; ROHS: Yes; Temp_Range: -40 to +125C
C66 C110 C978 = CAP_NP: CAP CER 1uF 16V 10% X5R 0402; AGILE_PN: 150-78973; CAD_APPROVED: Yes; FPLIST: CC0402_25,CC0402_HD,0402_CC; HEIGHT: 0.55 MM; MFG_NAME01: YAGEO; MFG_PN01: CC0402KRX5R7BB105; ROHS: Yes; Tolerance: 10%; VOLTAGE: 16V
C71 C80 = CAP_NP: CAP CER 15PF 100V +/-0.5PF C0G 0603; AGILE_PN: 150-75134; CAD_APPROVED: Yes; FPLIST: CC0603_OV,CC0603,0603_CC; HEIGHT: 0.87 MM; MFG_NAME01: KEMET; MFG_PN01: C0603C150D1GAC; ROHS: Yes; Tolerance: 0.5PF; VOLTAGE: 100V
C73 C79 = CAP_NP: CAP CER 7.5pF 250V 3.3% C0G 0603; AGILE_PN: 150-79186; CAD_APPROVED: Yes; FPLIST: CC0603_OV,CC0603,0603_CC; HEIGHT: 0.89MM; MFG_NAME01: Murata; MFG_PN01: GQM1875C2E7R5CB12; ROHS: Yes; Tolerance: +/-0.25pF; VOLTAGE: 250V
C74 C76 = CAP_NP: CAP CER 0.33uF 16V 10% X5R 0402; AGILE_PN: 150-79409; CAD_APPROVED: Yes; FPLIST: CC0402_25,CC0402_HD,0402_CC; HEIGHT: 0.55MM; MFG_NAME01: TDK; MFG_PN01: C1005X5R1C334K050BC; ROHS: Yes; Tolerance: 10%; VOLTAGE: 16V
C75 = CAP_NP: CAP CER 1000PF 100V 10% X7R 0603; AGILE_PN: 150-77156; CAD_APPROVED: Yes; FPLIST: CC0603_OV,CC0603,0603_CC; HEIGHT: 0.95MM; MFG_NAME01: KEMET; MFG_PN01: C0603C102K1RACTU; ROHS: Yes; Tolerance: 10%; VOLTAGE: 100V
C81-C85 = CAP_NP: CAP CER 0.1uF 100V 5% C0G 1206; AGILE_PN: 150-79740; CAD_APPROVED: Yes; FPLIST: CC1206_OV,CC1206,1206_CC; HEIGHT: 1.8MM; MFG_NAME01: MURATA; MFG_PN01: GRM31C5C2A104JA01; ROHS: Yes; Tolerance: 5%; VOLTAGE: 100V
C87 = CAP_NP: CAP CER 4700pF 100V 5% C0G 0805; AGILE_PN: 150-78729; CAD_APPROVED: Yes; FPLIST: CC0805_OV,CC0805,0805_CC; HEIGHT: 0.88MM; MFG_NAME01: KEMET; MFG_PN01: C0805C472J1GACTU; ROHS: Yes; Tolerance: 5%; VOLTAGE: 100V
C106 C107 C977 C979 = CAP_NP: CAP CER 10UF 10V 10% X5R 0805; AGILE_PN: 150-75204; CAD_APPROVED: Yes; FPLIST: CC0805_OV,CC0805,0805_CC; HEIGHT: 1.6MM; MFG_NAME01: MURATA; MFG_PN01: GRM21BR61A106KE19_; ROHS: Yes; Tolerance: 10%; VOLTAGE: 10V
L6 = INDUCTOR: IND PWR 4.7uH@1MHZ 1000mA 20% 1008; AGILE_PN: 180-78134; CAD_APPROVED: Yes; HEIGHT: 1 MM; MFG_NAME01: Murata; MFG_PN01: LQH2HPN4R7MG0L; PART_TYPE: INDUCTOR\POWER; ROHS: Yes
R71 = RES: RES MF 0.010 OHM 1/2W 1% 1206; AGILE_PN: 470-77100; CAD_APPROVED: Yes; FPLIST: RC1206_OV,RC1206,1206_CC; HEIGHT: 0.95MM; MFG_NAME01: CYNTEC; MFG_PN01: RL1632H-R010-F-N; ROHS: Yes; Tolerance: %1
R72 R73 R79 R80 = RES: RES MF 3.32 OHM 1/10W 1% 0603; AGILE_PN: 470-75780; CAD_APPROVED: Yes; FPLIST: RC0603_OV,RC0603,0603_CC; HEIGHT: 0.55 MM; MFG_NAME01: VENKEL COMPANY; MFG_PN01: CR0603-10W-3R32FT; ROHS: Yes; Tolerance: 1%
R78 = RES: RES MF 51 OHM 1/10W 5% 0603; AGILE_PN: 470-75403; CAD_APPROVED: Yes; FPLIST: RC0603_OV,RC0603,0603_CC; HEIGHT: 0.55MM; MFG_NAME01: BOURNS; MFG_PN01: CR0603-JW-510ELF; ROHS: Yes; Tolerance: 5%
TP44 TP45 = TEST_POINT_10-201-X: TEST POINT.094X.186 PIN AG TH; AGILE_PN: 280-75144; ASSY_OPT: DNP; CAD_APPROVED: YES; HEIGHT: 4.73 MM; MFG_NAME01: CONCORD ELECTRONICS; MFG_PN01: 10-201-3-01+; ROHS: Yes
TP52 = Test_pad: TEST PAD 70MIL ROUND SMT; NO PART TO ORDER; AGILE_PN: 510-75218; ASSY_OPT: DNP; CAD_APPROVED: Yes; HEIGHT: 0.1 MM; ROHS: Yes
U6 = INA214_AMP_6P: IC LIN AMP CURRENT SENSE 100V/V 14KHZ 2.7-26V SC70-6; AGILE_PN: 315-81377; CAD_APPROVED: Yes; HEIGHT: 1.1MM; MFG_NAME01: Texas Instruments; ROHS: Yes; Temp_Range: -40C to 125C
U14 = SCT63240

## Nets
GND: C1.2 C5.2 C7.2 C8.2 C9.2 C10.1 C11.1 C12.2 C13.1 C14.2 C16.2 C17.2 C26.1 C27.2 C28.1 C29.2 C32.2 C33.2 C34.2 C35.2 C36.2 C37.1 C38.2 C39.2 C40.2 C42.2 C44.2 C45.1 C46.2 C47.2 C58.2 C59.2 C61.2 C62.2 C63.2 C71.1 C73.1 C79.2 C80.2 C106.2 C107.2 C109.1 C110.2 C113.2 C121.2 C975.2 C977.2 C978.2 C979.2 C980.1 C981.1 C982.2 FL1.3 J3.2 J3.4 J3.6 J4.5(A3) J4.6(B3) J5.2 Q4.2(SOURCE) R15.2 R16.2 R33.2 R37.2 R54.1 R62.1 R79.2 R80.2 R121.2 R711.2 TP30.1(Pin1) U1.17(GND) U4.7(GND_1) U4.8(GND_2) U4.18(GND_3) U4.21(EPAD) U13.22(VSS_1) U13.31(VSS_2) U13.45(VSS_3) U14.2(PGND) U14.5(GND) U14.16(AGND)
GNDA: C15.2 C19.2 C20.1 C21.2 C22.2 C23.2 C30.1 C31.2 C51.2 C53.2 C54.2 C55.2 C56.1 D6.1 D13.1 J6.1 R21.2 R27.2 R30.2 R37.1 R66.1 R92.1 RT1.1 U5.2(V-) U6.1(REF) U6.2(GND) U13.16(VSSA)
V3.3: C11.2 C12.1 C16.1 C26.2 C27.1 C28.2 C29.1 C34.1 C107.1 D4.A(ANODE) D5.A(ANODE) J3.11 J4.7(A4) J4.8(B4) J5.1 L2.1 L7.2 R7.1 R38.1 R39.2 R40.1 R41.2 R43.2 R44.2 R115.1 TP28.1(Pin1) U1.3(VDD) U13.32(VDD_1) U13.44(VDD_2)
V3.3A: C30.2 C31.1 C51.1 C56.2 D6.2 D13.2 L2.2 R64.2 R67.2 R69.2 R88.1 U5.5(V+) U6.3(V+) U13.15(VDDA)
VIN+: C4.1 F1.1 J1.1 J2.A4(VBUS1) J2.A9(VBUS2) J2.B4(VBUS4) J2.B9(VBUS3)
VIN_SW: C1.1 C8.1 C9.1 C36.1 C37.2 C38.1 C39.1 C40.1 C982.1 L1.2 R28.1 TP2.1(Pin1) U1.15(VBUS) U4.2(IN_1) U4.3(IN_2) U4.4(IN_3) U4.5(IN_4) U14.4(VIN)
VINSW_SENSE: C23.1 R28.2 R30.1 U13.14(GPIOB4/ANB4_CMPC_IN1)
AC_COIL_CURRENT_OP: C20.2 D13.3 R87.2 R88.2 R92.2 TP48.1(Pin1) U13.17(GPIOB0/ANB0_CMPB_IN3)
BAT-: C2.2 C3.2 C4.2 D2.A D3.A FL1.4 J1.2 J1.3 J2.A1(GND1) J2.A12(GND2) J2.B1(GND4) J2.B12(GND3) J2.SH1 J2.SH2 J2.SH3 J2.SH4 TVS1.A U2.B1(GND)
COIL_PWM_LH: R33.1 TP38.1(Pin1) U13.34(GPIOE1/PWM_0A) U14.18(PWM1)
COIL_PWM_LL: R121.1 TP57.1(Pin1) U13.33(GPIOE0/PWM_0B) U14.17(PWM2)
COILS: C52.1 C79.1 C80.1 C81.2 C82.2 C83.2 C84.2 C85.2 C87.1 R78.2 TP45.1
CONN_CC1: D2.C J2.A5(CC1) U1.13(CC1)
CONN_CC2: D3.C J2.B5(CC2) U1.14(CC2)
CONN_DN: J2.A7(DN1) J2.B7(DN2) R11.2 R14.1 R15.1 U2.A2(CH1_IN-) U2.C2(CH1_OUT-)
CONN_DP: J2.A6(DP1) J2.B6(DP2) R12.1 R13.1 R16.1 U2.A1(CH1_IN+) U2.C1(CH1_OUT+)
CTRL_DN_0: R11.1 U13.26(GPIOC9/SCLK0/XB_IN4/TXD0/XB_OUT8)
CTRL_DN_1: R14.2 U13.27(GPIOC10/MOSI0/XB_IN5/MISO0/XB_OUT9)
CTRL_DP_0: R12.2 U13.29(GPIOC11/CANTX/SCL0/TXD1)
CTRL_DP_1: R13.2 U13.30(GPIOC12/CANRX/SDA0/RXD1)
DAC_O: TP9.1(Pin1) U13.13(GPIOC5/DACA_O/XB_IN7)
DCDC_EN: R54.2 U4.11(EN) U4.12(MODE) U13.28(GPIOF0/XB_IN6/SCLK1)
DDMTOGGLE: U13.23(GPIOC6/TA2/XB_IN3/CMP_REF/~{SS0})
DRV_EN_H: U13.25(GPIOC8/MISO0/RXD0/XB_IN9/XB_OUT6)
DRV_EN_L: U13.24(GPIOC7/~{SS0}/TXD0/XB_IN8)
EXTAL: R35.1 U13.3(GPIOC0/EXTAL/CLKIN0)
FRS_EN: TP6.1(TP) U1.1(FRS_EN)
FSKOUTPUT: TP13.1(Pin1) U13.35(GPIOE2/PWM_1B)
HB1A: C70.2 C71.2 C73.2 C75.1 C77.1 TP44.1
INPUT_CURR_HW_OCP: C21.1 R24.2 TP20.1(Pin1) U13.18(GPIOB1/ANB1_CMPB_IN0/DACB_O)
INPUT_CURR_IN: C15.1 R17.2 U13.11(GPIOA2/ANA2_VREFHA_CMPA_IN1)
INPUT_CURRENT: R17.1 R24.1 TP41.1(Pin1) U6.6(OUT)
LED1: R46.2 U13.39(GPIOE4/PWM_2B/XB_IN2)
LED2: R45.2 U13.40(GPIOE5/PWM_2A/XB_IN3)
nINT: R7.2 TP15.1(Pin1) U1.10(ALERT_N) U13.37(GPIOC13/TA3/XB_IN6/~{EWM_OUT})
nRST: C35.1 J3.9 R39.1 TP25.1(Pin1) U13.2(GPIOD4/~{RESET})
PG1: U4.9(PG)
Q_RESONANCE_VOLT: C53.1 R65.2 TP40.1(Pin1) U13.21(GPIOB3/ANB3_VREFLB_CMPC_IN0)
RAIL_CTRL_PWM: R125.1 TP10.1(Pin1) U13.7(GPIOC4/TA1/CMPB_O/XB_IN6/~{EWM_OUT})
RAIL_DIS: R61.1 U13.38(GPIOF1/CLKO1/XB_IN7/CMPD_O)
RXD0: J4.3(A2) R41.1 TP34.1(Pin1) U13.6(GPIOC3/TA0/CMPA_O/RXD0/CLKIN1)
SCL0: J5.3 R43.1 U1.8(I2C_SCL) U13.42(GPIOC15/SCL0/XB_OUT5/PWM_FAULT5)
SDA0: J5.4 R44.1 U1.7(I2C_SDA) U13.41(GPIOC14/SDA0/XB_OUT4/PWM_FAULT4)
SLV_ADDR: R9.2 U1.5(SLV_ADDR)
TCK: J3.5 R40.2 TP29.1(Pin1) U13.1(GPIOD2/TCK)
TDI: J3.1 TP26.1(Pin1) U13.48(GPIOD0/TDI)
TDO: J3.3 TP27.1(Pin1) U13.46(GPIOD1/TDO)
TEMP1: C54.1 R68.2 U13.9(GPIOA0/ANA0_CMPA_IN3/CMPC_O)
TEMP2: C55.1 R70.2 U13.10(GPIOA1/ANA1_CMPA_IN0)
TMS: J3.10 R38.2 TP31.1(Pin1) U13.47(GPIOD3/TMS)
TXD0: J4.1(A1) TP35.1(Pin1) U13.5(GPIOC2/TXD0/XB_OUT11/XB_IN2/CLKO0)
VCAP1: C14.1 U13.19(VCAP_1)
VCAP2: C17.1 U13.43(VCAP_2)
VRAIL: C42.1 C44.1 C45.2 C46.1 C47.1 C66.1 C974.1 L301.2 R19.1 R71.1 R710.1 TP39.1(Pin1) U6.4(+IN)
VRAIL_SENSE: C19.1 R22.2 TP17.1(Pin1) U13.12(GPIOA3/ANA3_VREFLA_CMPA_IN2)
VRAILA: C58.1 C59.1 C62.1 C63.1 C66.2 C980.2 C981.2 R23.1 R58.1 R71.2 R72.1 R73.1 U6.5(-IN) U14.1(PVIN1) U14.3(PVIN2)
VRAILA_SENSE: C22.1 R23.2 R27.1 U13.20(GPIOB2/ANB2_VERFHB_CMPC_IN3)
XTAL: R34.1 U13.4(GPIOC1/XTAL)
N21191849: C2.1 C3.1 F1.2 FL1.1 TVS1.C
N22930980: C5.1 C7.1 FL1.2 L1.1
N34183122: R65.1 U5.3(-IN) U5.4(OUT)
N34183222: C52.2 D6.3 R64.1 R66.2 U5.1(+IN)
N34183302: Q4.1(GATE) R61.2 R62.2
N34183308: Q4.3(DRAIN) R58.2
N34307564: C72.2 C76.1 C78.1 C81.1 C82.1 C83.1 C84.1 C85.1 U14.11(SW2)
N34307568: C75.2 R78.1
N34317060: TP7.1(TP) U1.9(DBG_ACC)
N34317070: TP8.1(TP) U1.6(ILIM_5V_VBUS)
N34317109: TP5.1(TP) U1.2(EN_SNK1)
N34317115: R10.1 U1.11(FAULT_N)
N34317133: C13.2 R9.1 R10.2 U1.4(BYPASS)
N34317236: C10.2 R115.2 U1.12(VCONN_IN)
N34323245: R19.2 R21.1 R22.1
N34324485: D5.C(CATHODE) R46.1
N34324487: D4.C(CATHODE) R45.1
N34325643: C33.1 R35.2 R36.2 Y2.2
N34325645: C32.1 R34.2 R36.1 Y2.1
N34329684: C77.2 R79.1
N34329686: C70.1 R72.2
N34332746: C72.1 R73.2
N34332748: C78.2 R80.1
N34338258: J6.2 R69.1 R70.1
N34338338: R67.1 R68.1 RT1.2
N34356239: C74.2 U14.12(SW1)
N34412396: TP60.1(Pin1) U13.8(GPIOA4/ANA4_CMPD_IN0)
N34495361: C74.1 R761.2
N34606751: TP4.1(TP) U1.16(EN_SRC)
N34618435: C121.1 U4.17(VCC)
N34618513: C896.1 U4.1(BS)
N34618515: C896.2 L301.1 U4.6(LX_1) U4.19(LX_2) U4.20(LX_3)
N34618589: C974.2 R710.2 R711.1 R759.1 U4.14(FB)
N34618608: C975.1 U4.15(BYP)
N34618678: C113.1 R125.2 R759.2
N34619941: R761.1 U14.13(BST1)
N34620056: C76.2 R762.2
N34620061: R762.1 U14.10(BST2)
N34621679: C976.1 L6.1 U14.6(SW3)
N34621693: C976.2 U14.7(BST3)
N34621952: C61.1 C106.1 C109.2 C110.1 C977.1 L6.2 TP52.1(Pin1) U14.8(VDD)
N34622557: C978.1 TP69.1(Pin1) U14.14(VREF)
N34622800: C979.1 L7.1 U14.9(V3P3)
N34624994: TP70.1(Pin1) U14.15(ISNS)
N34627588: C87.2 R87.1

Not connected (* = marked no-connect by the designer): J2 A2(SSTXP1)* A3(SSTXN1)* A8(SBU1)* A10(SSRXN2)* A11(SSRXP2)* B2(SSTXP2)* B3(SSTXN2)* B8(SBU2)* B10(SSRXN1)* B11(SSRXP1)*; J3 7 8 12 13 14; J4 2(B1) 4(B2); U4 10(NC_1) 13(ILMT) 16(NC_2); U13 36(GPIOE3/PWM_1A); U14 19(EN)

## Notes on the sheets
sheet 1
- REVISION HISTORY
- DATE
- REV
- CHANGE DESCRIPTION
- System Block Diagram
- 04/11/2018
- V0.9
- - initial design
- SCT power stage application
- 19/03/2019
- B
- Sampling Circuits
- USB-PD 5~19V/ QC2.0/3.0
- Input Current
- Input Voltage
- VIN
- VIN
- Powerstage
- Powerstage
- VOUT
- VOUT
- Temperature
- 5V
- 3.3V
- VRail Set
- WCT1012VLF
- FB PWM
- BUCK
- MOS DRIVER
- Rail
  Voltage
- Full
  Bridge
- CONSOLE
- FreeMaster
- HB1A
- Resonant Circuits
- COIL
- HB1B
- 500nF
- Q factor
  detection
- WCT
- Q Factor Detection
- DDM
- DDM
- RC Circuits
- WCT
- SCH-32212 PDF: SPF-32212
- B
sheet 2
- Power Connector
- Bi-directional TVS
- option for USB-PD
- QC2.0
- SCH-32212 PDF: SPF-32212
- B
sheet 3
- FOD
- DDM
- FOD
  Rail Voltage
- Pin32
- Pin44
- Pin15
- Status LEDs
- JTAG
- FreeMaster
- For backup
- SCH-32212 PDF: SPF-32212
- B
- SCH-32212 PDF: SPF-32212
- A
sheet 4
- TX surface temperature sensing
- SCH-32212 PDF: SPF-32212
- B
sheet 5
- FOD
  Inverter Input Current
- TX COIL
- Qi RX
- DDM
- FOD
  AC Coil Current
- SCH-32212 PDF: SPF-32212
- B
